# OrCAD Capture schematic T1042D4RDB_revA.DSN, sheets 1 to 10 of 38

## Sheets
1 01 Page Listing: title: T104XRDB; rev: A
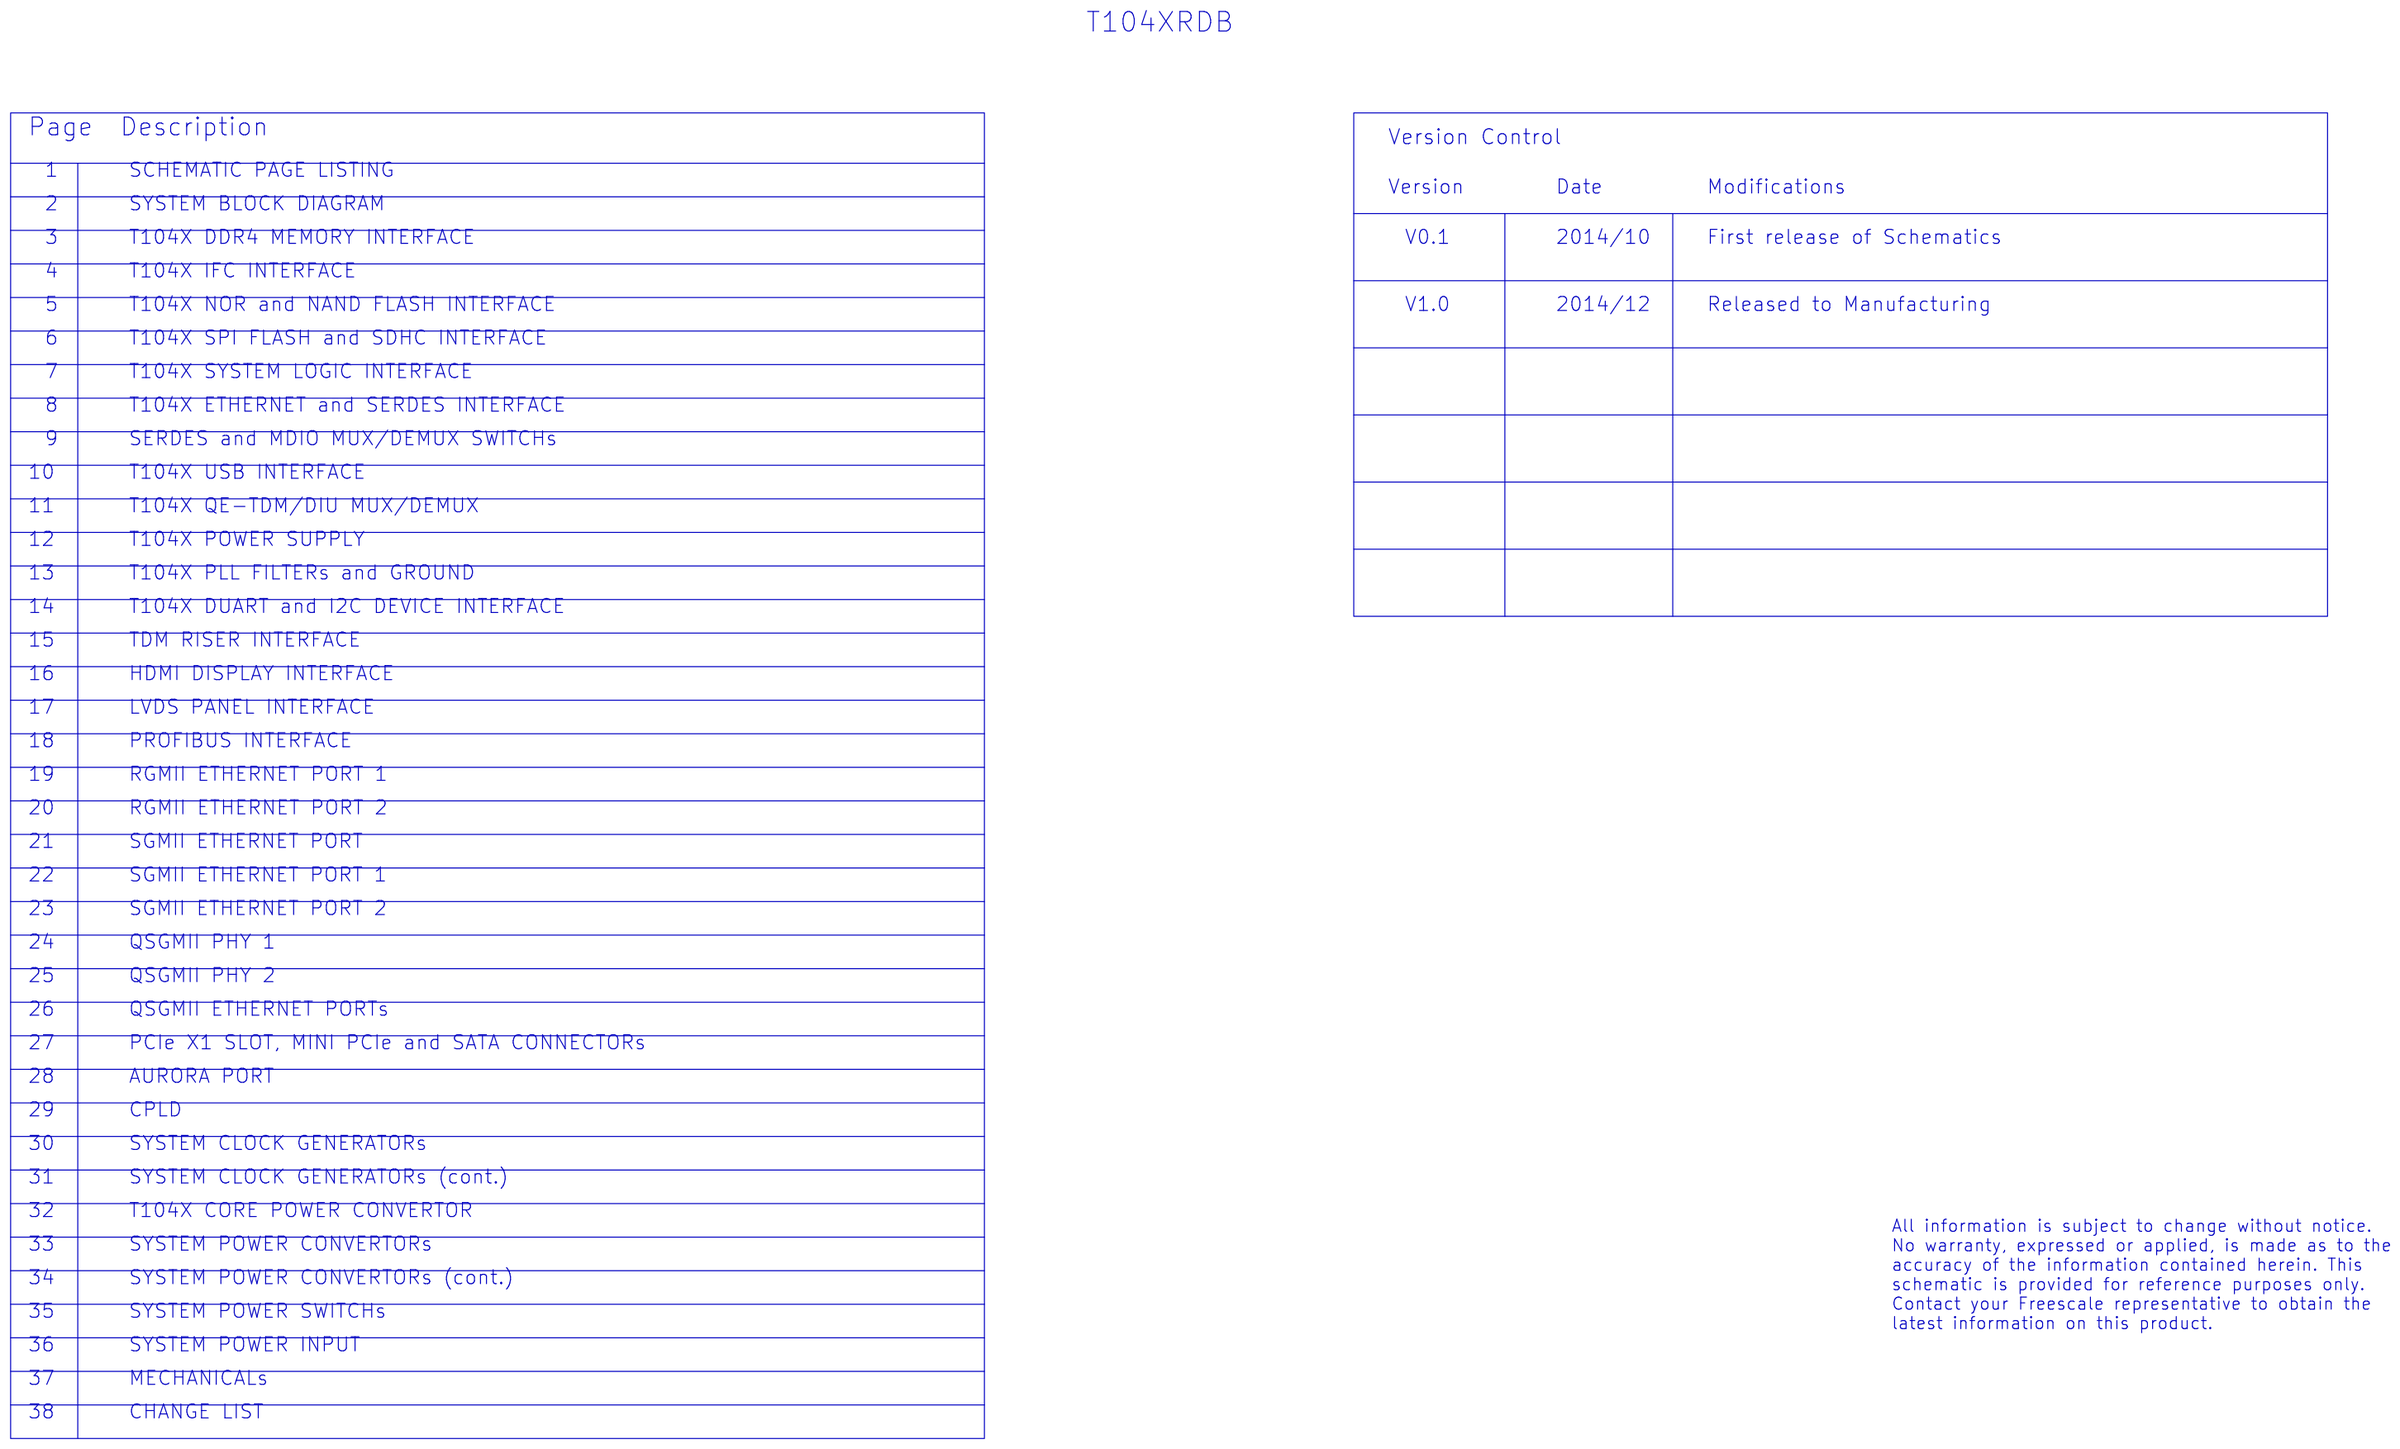
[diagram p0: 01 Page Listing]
2 02 Block Diagram
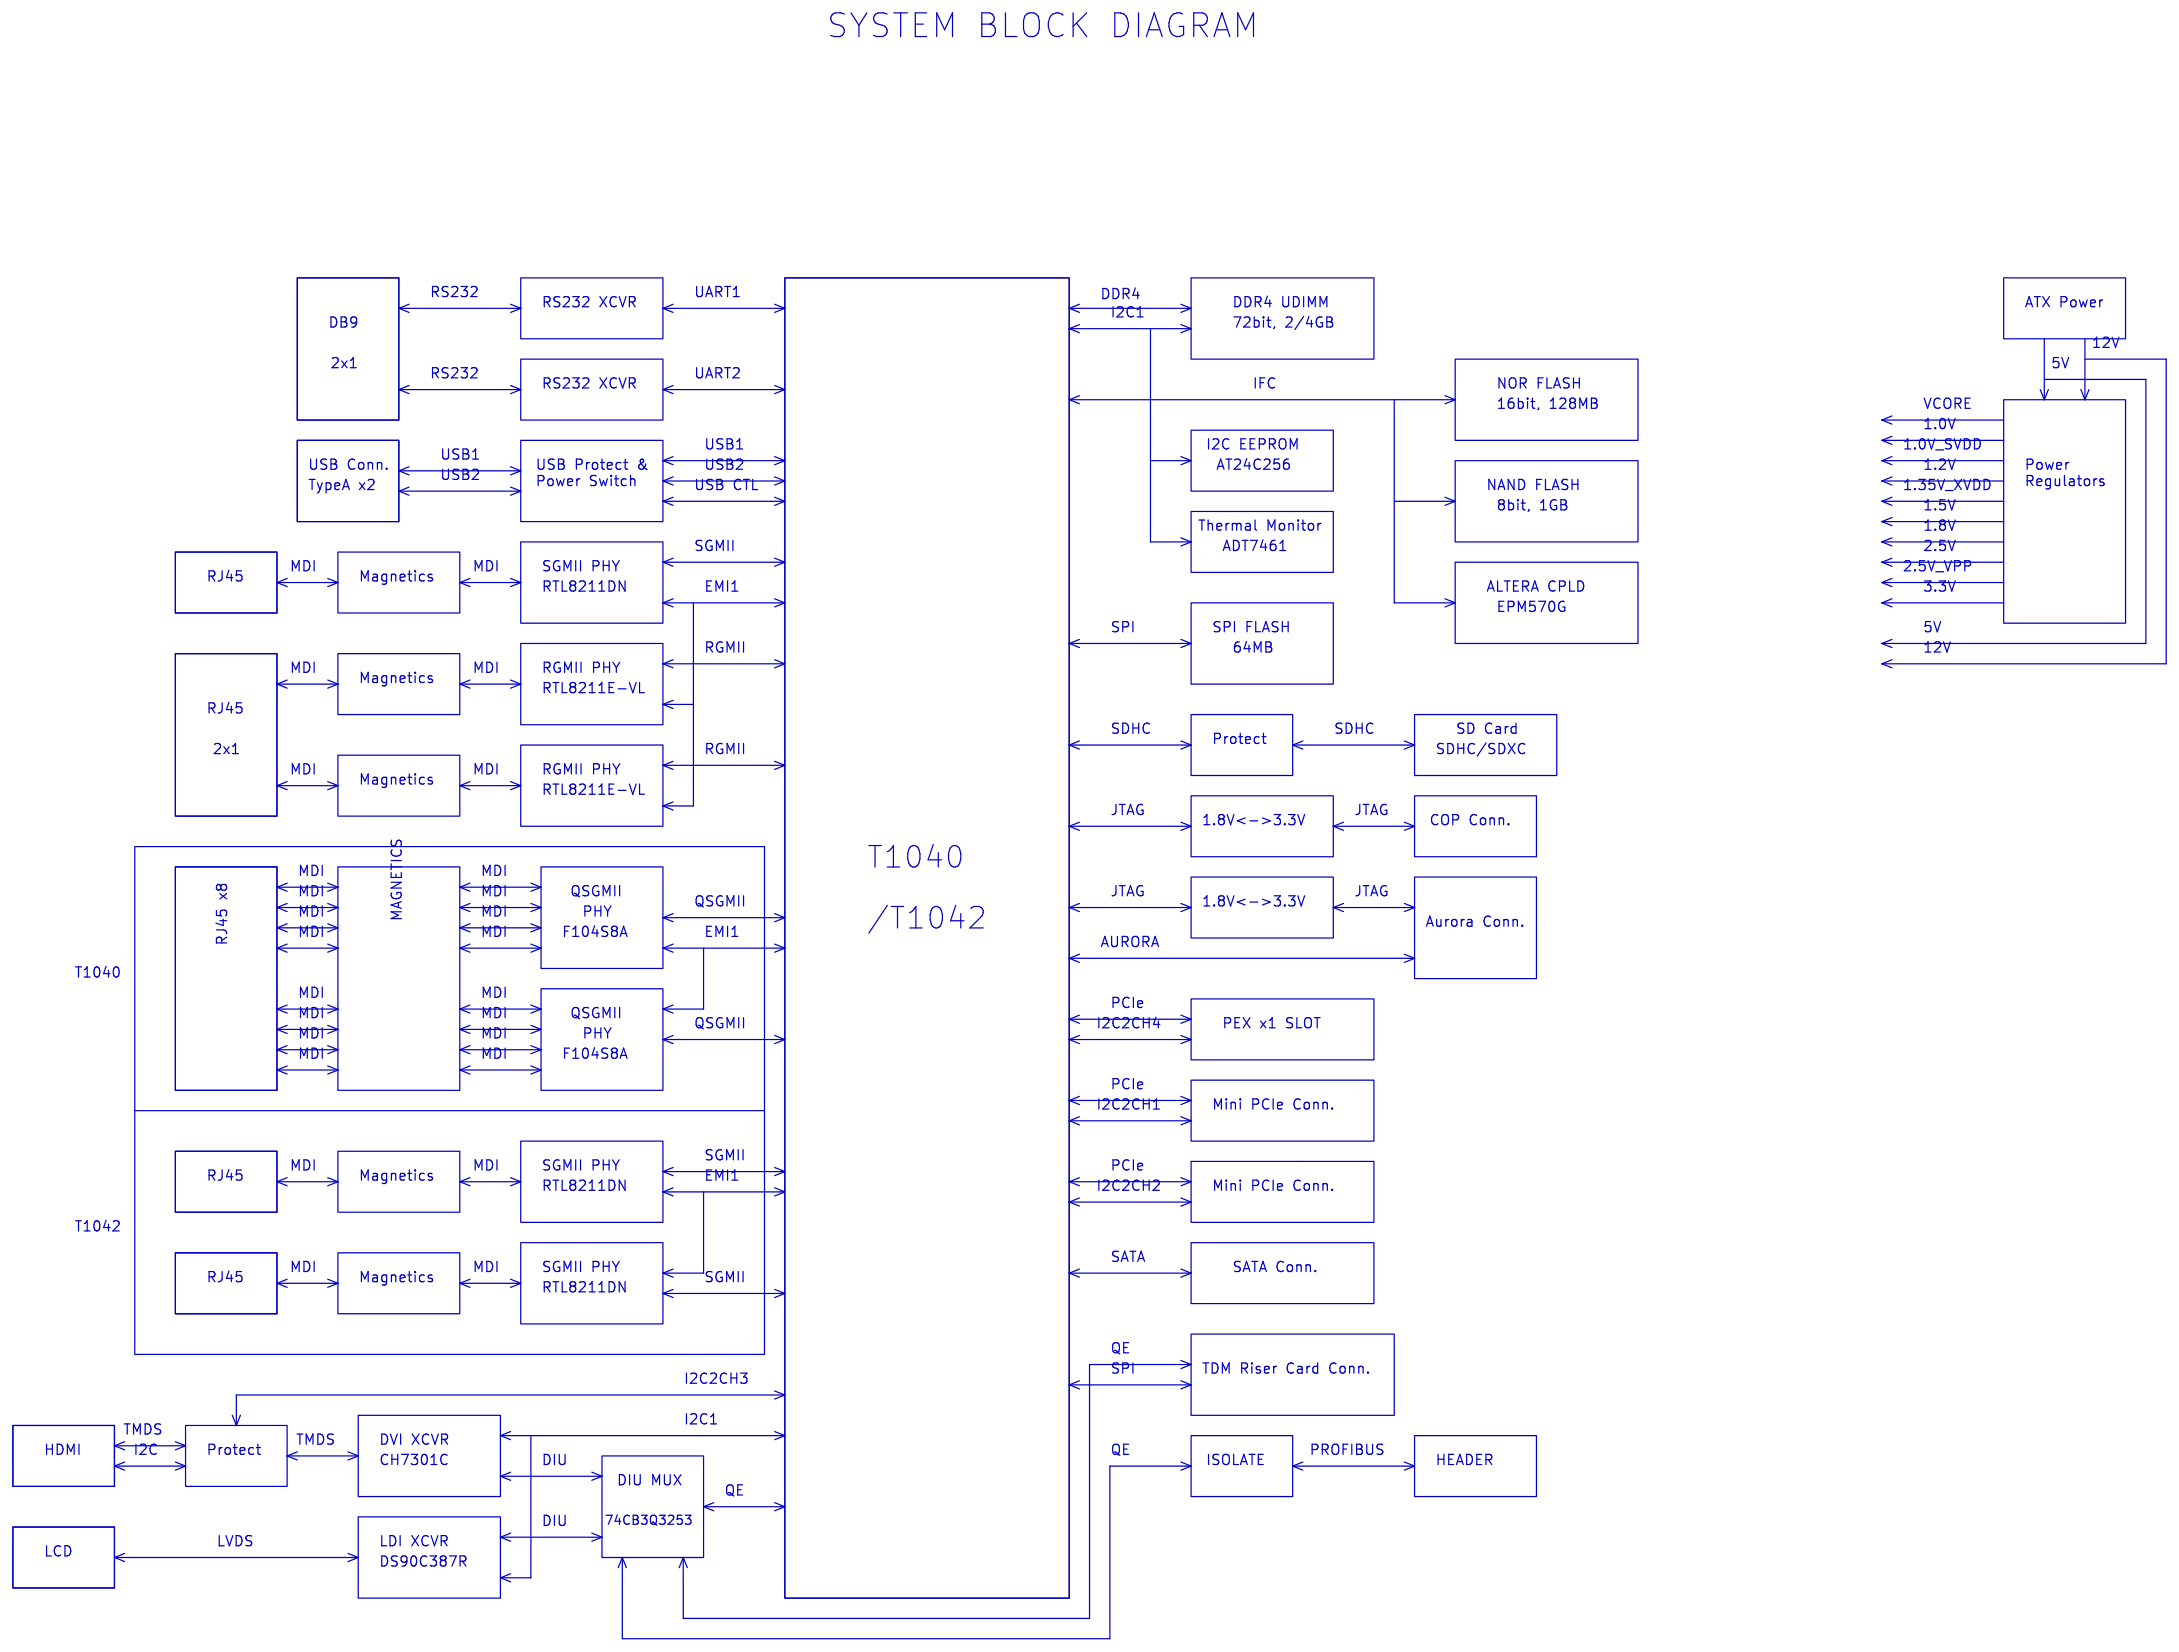
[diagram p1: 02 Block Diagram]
3 03 DDR4: size B
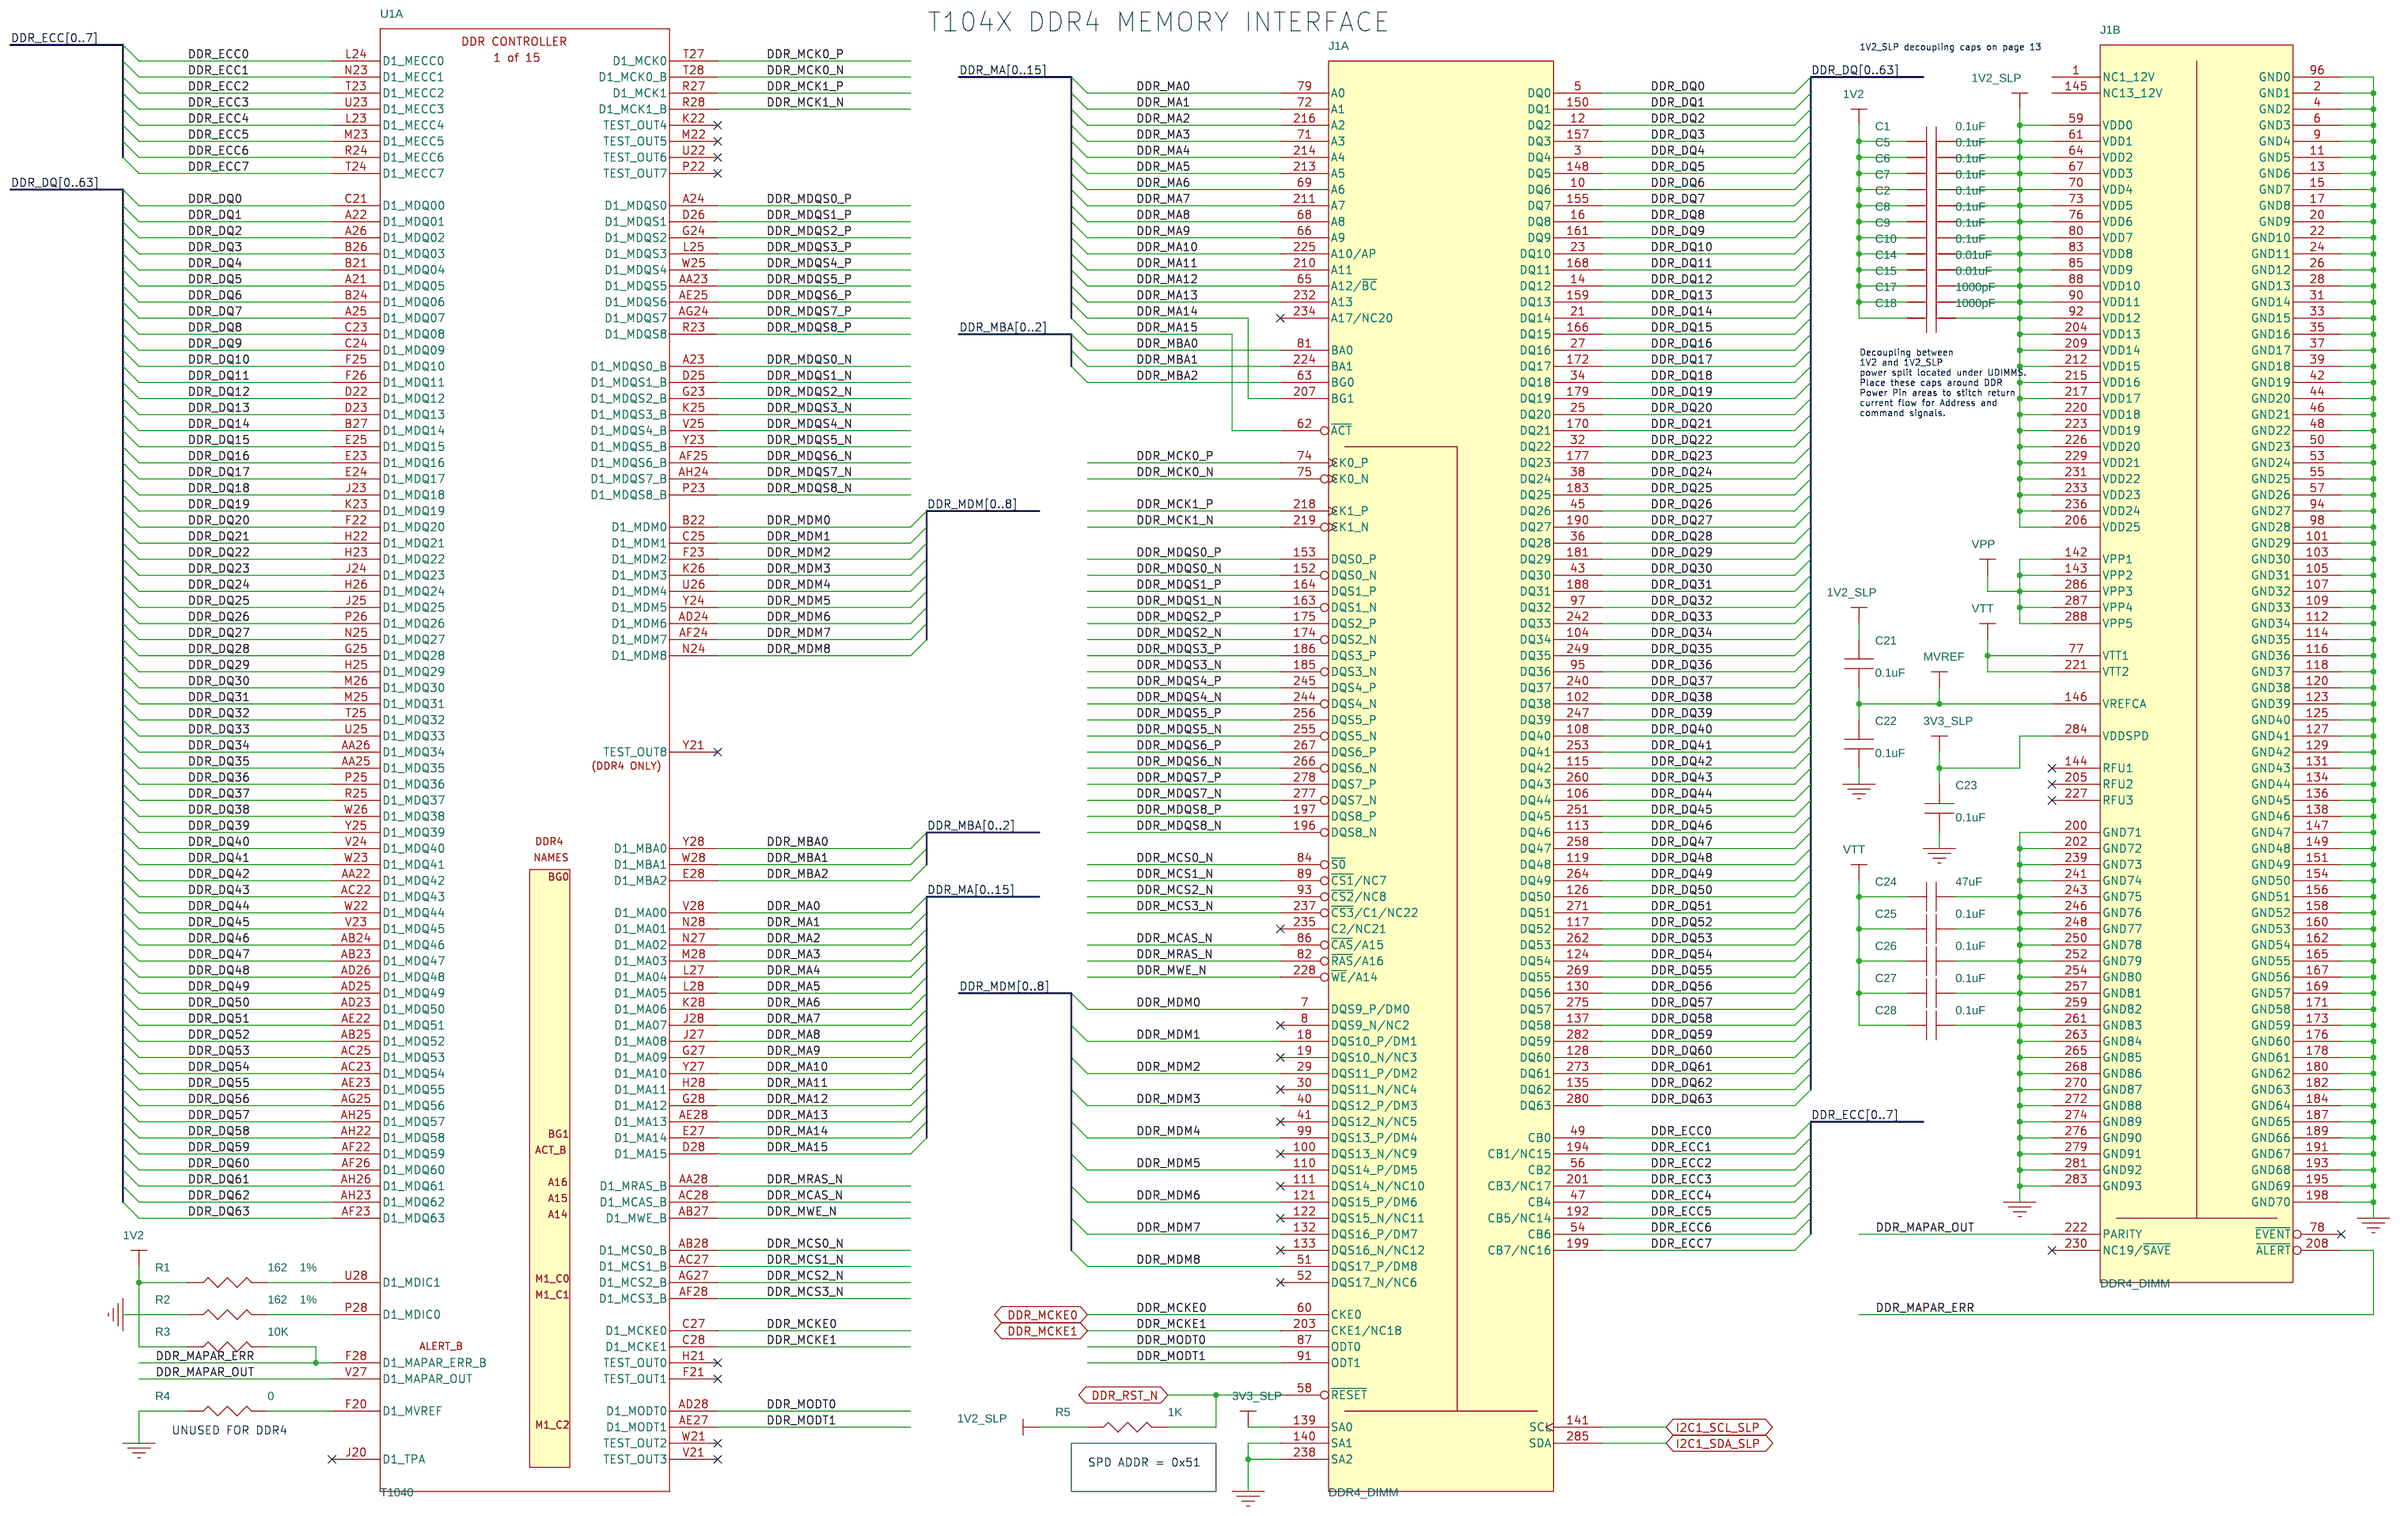
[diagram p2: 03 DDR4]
4 04 IFC: size B
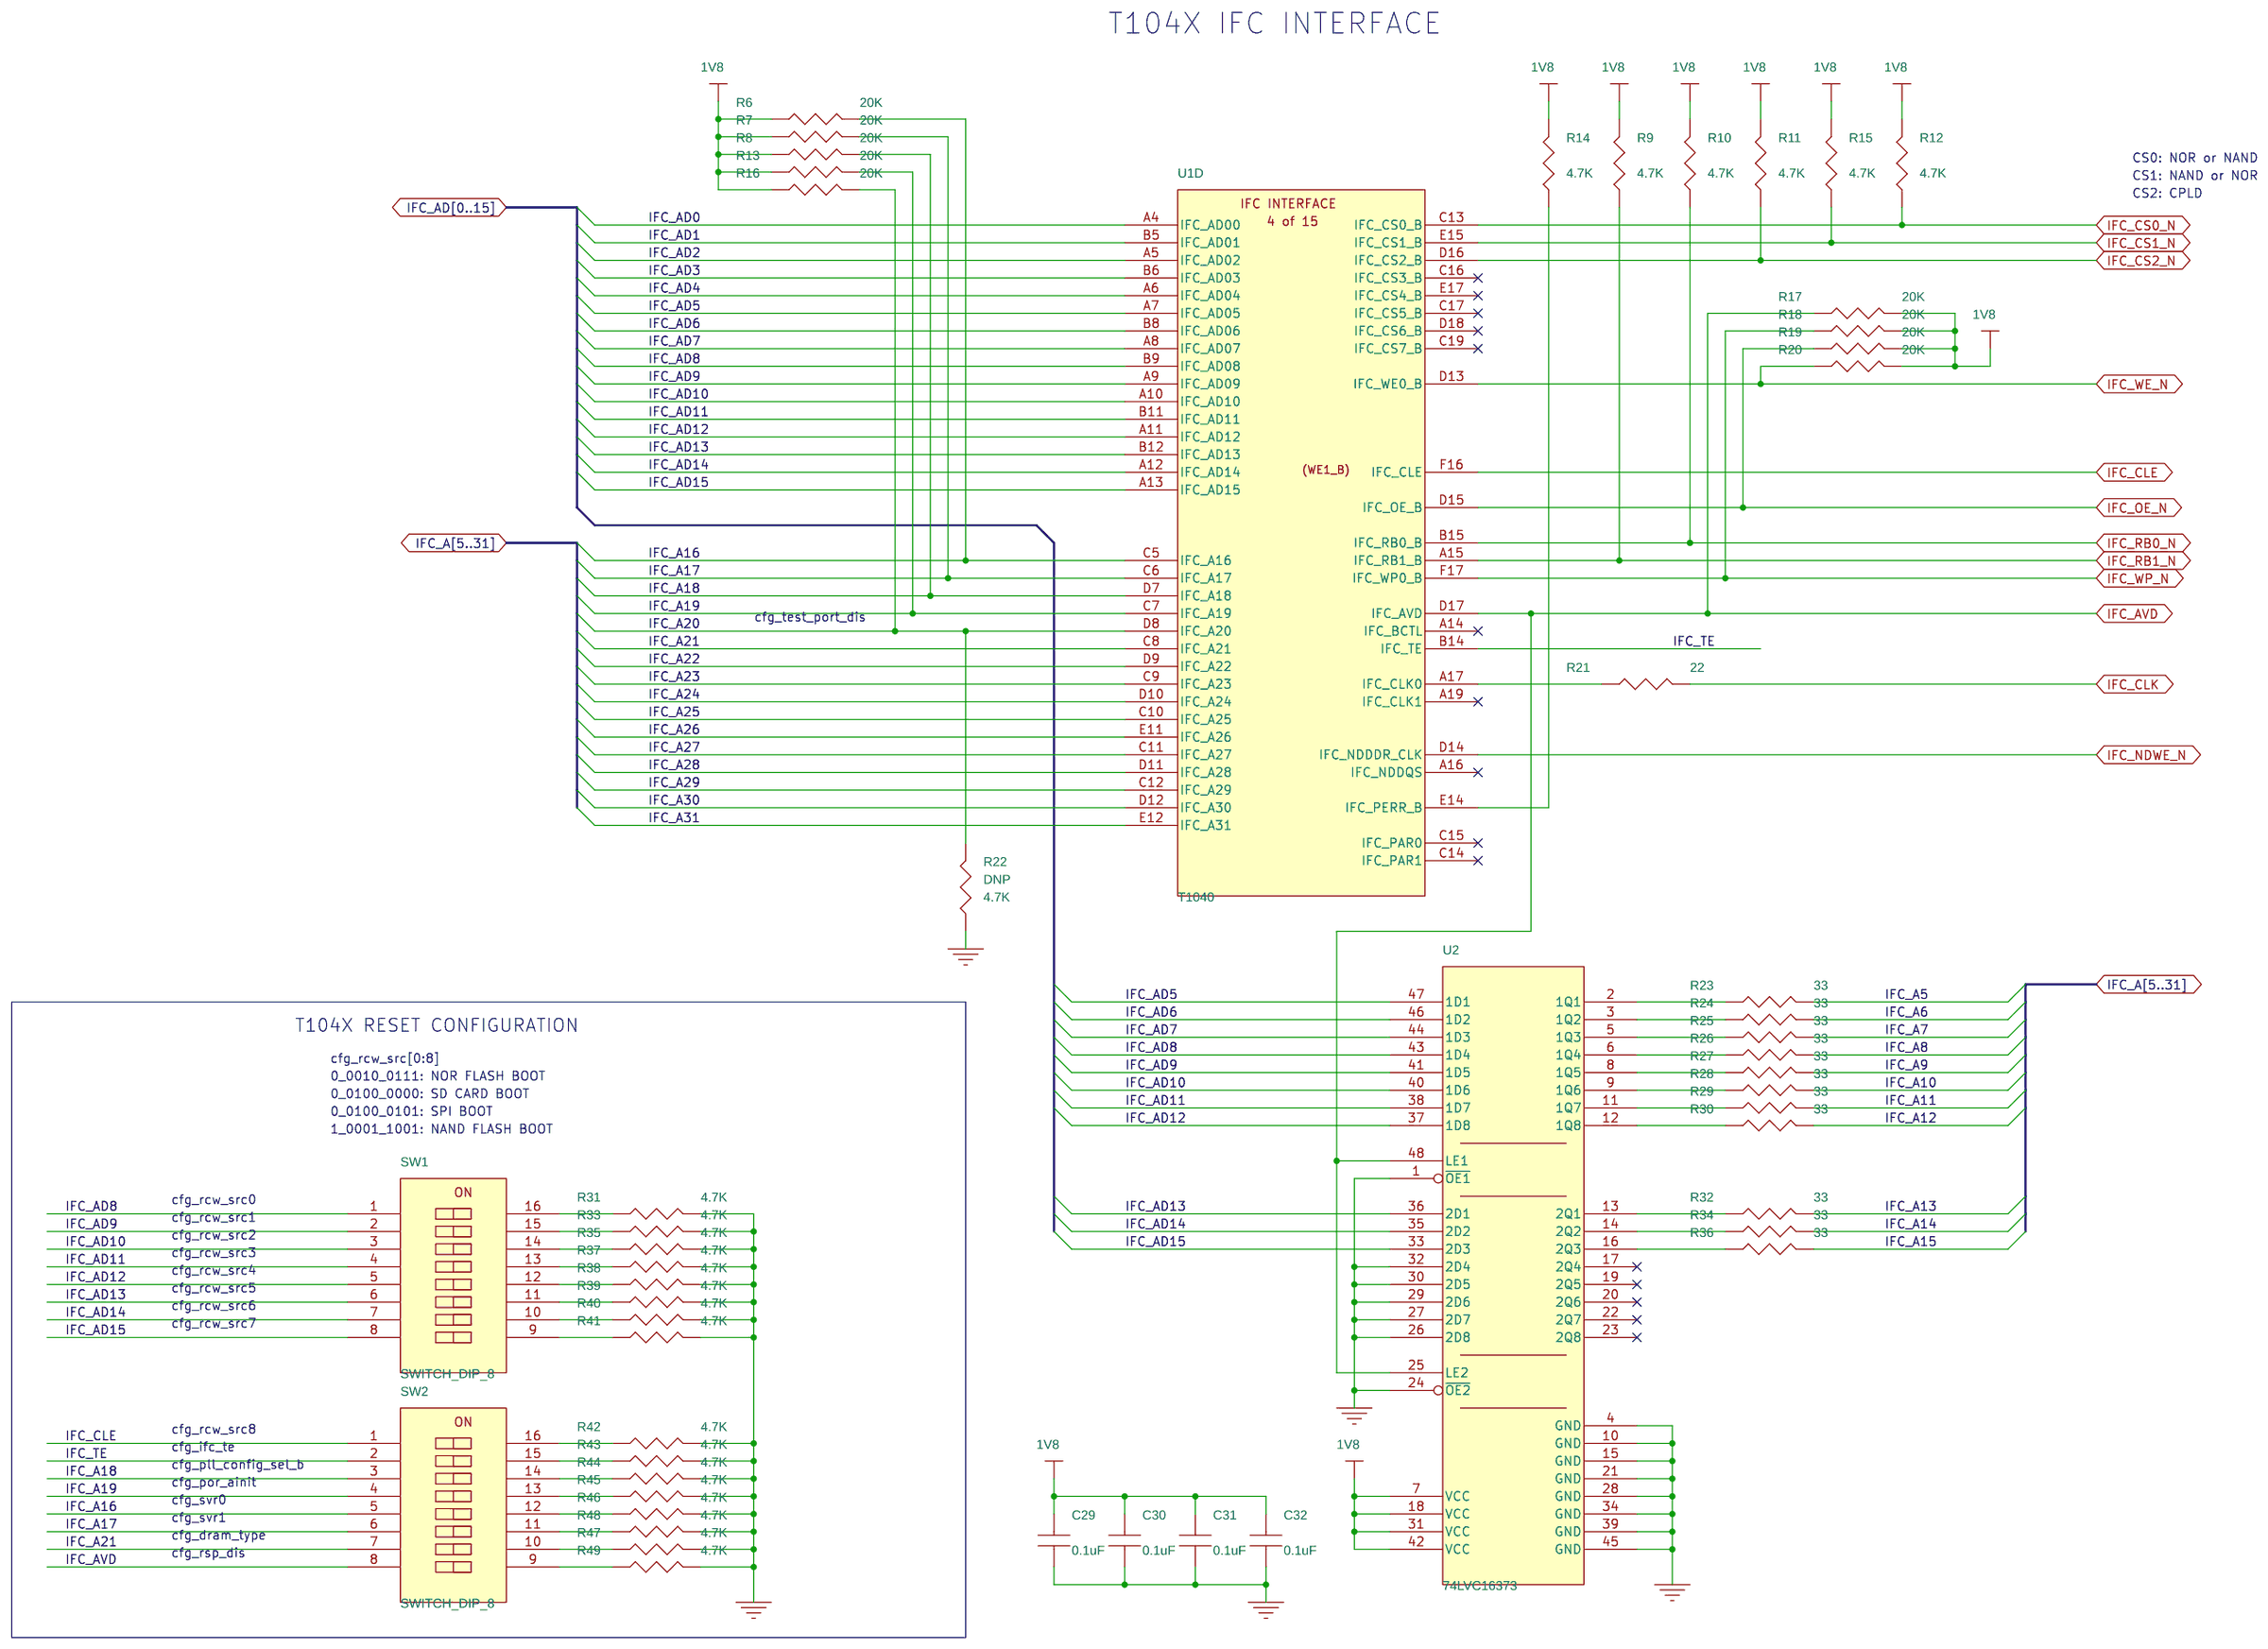
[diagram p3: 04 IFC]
5 05 Flash: size B
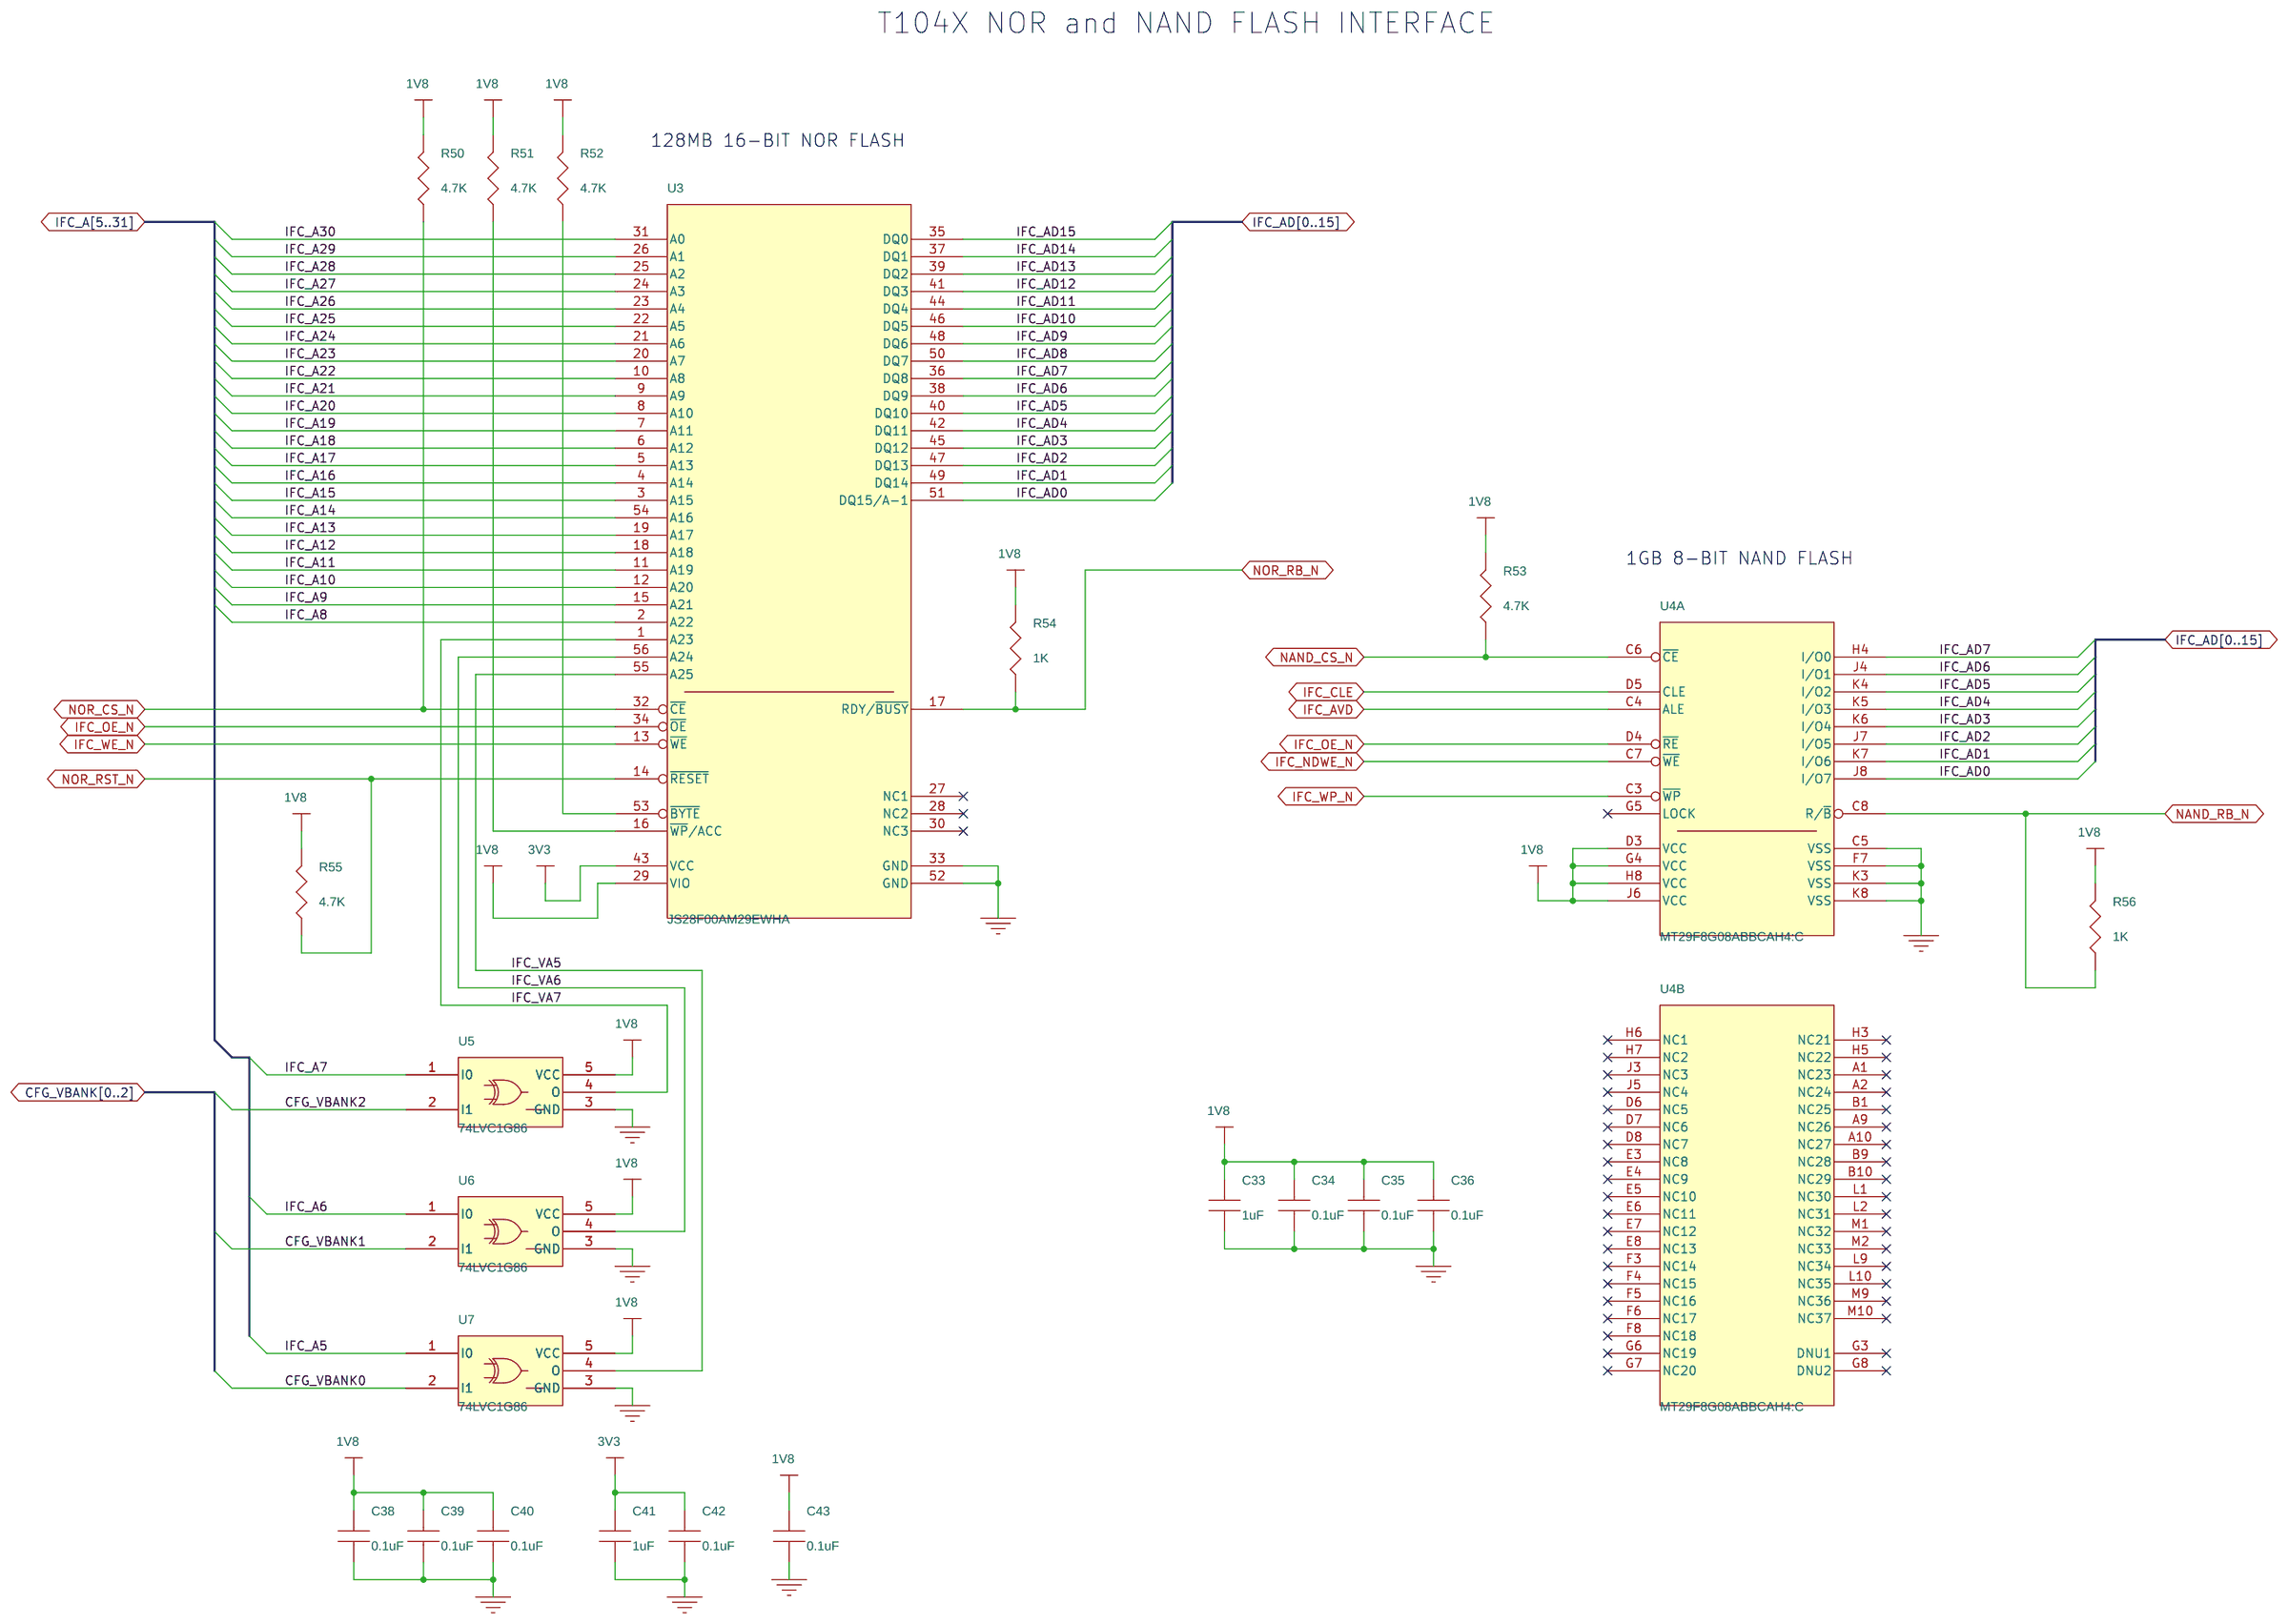
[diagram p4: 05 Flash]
6 06 SPI&SDHC: size B
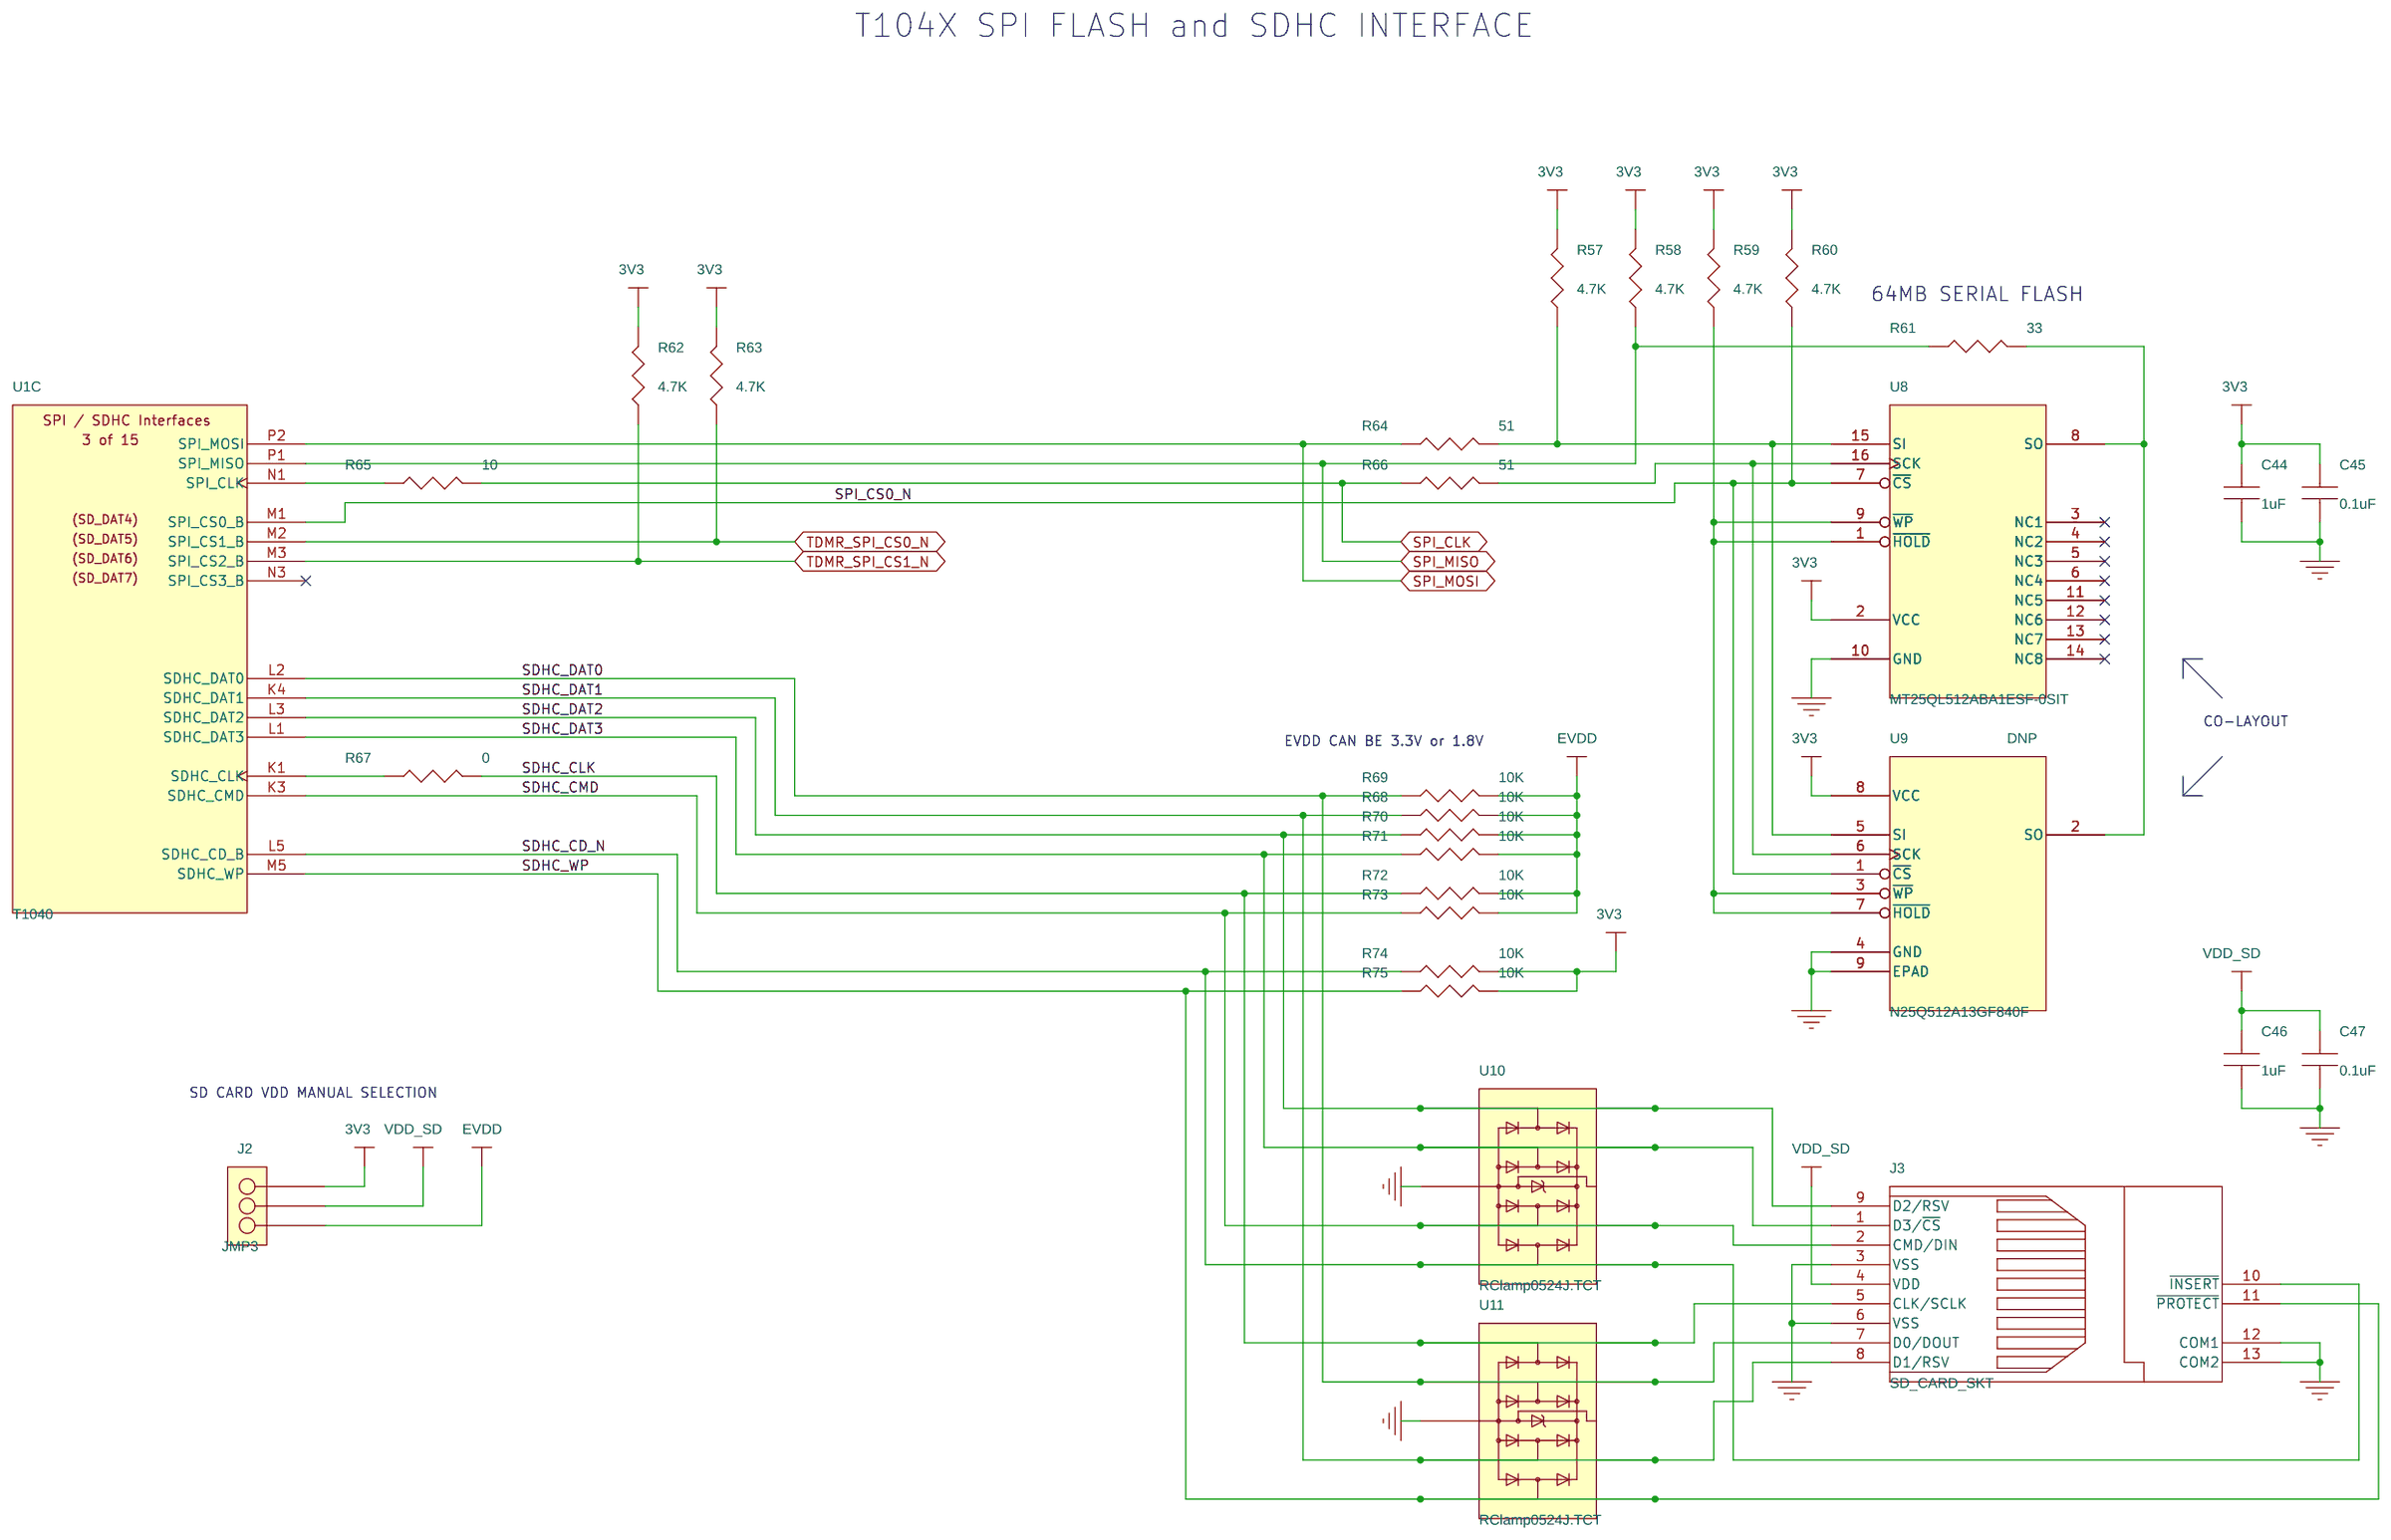
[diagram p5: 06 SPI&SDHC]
7 07 SYS: size B
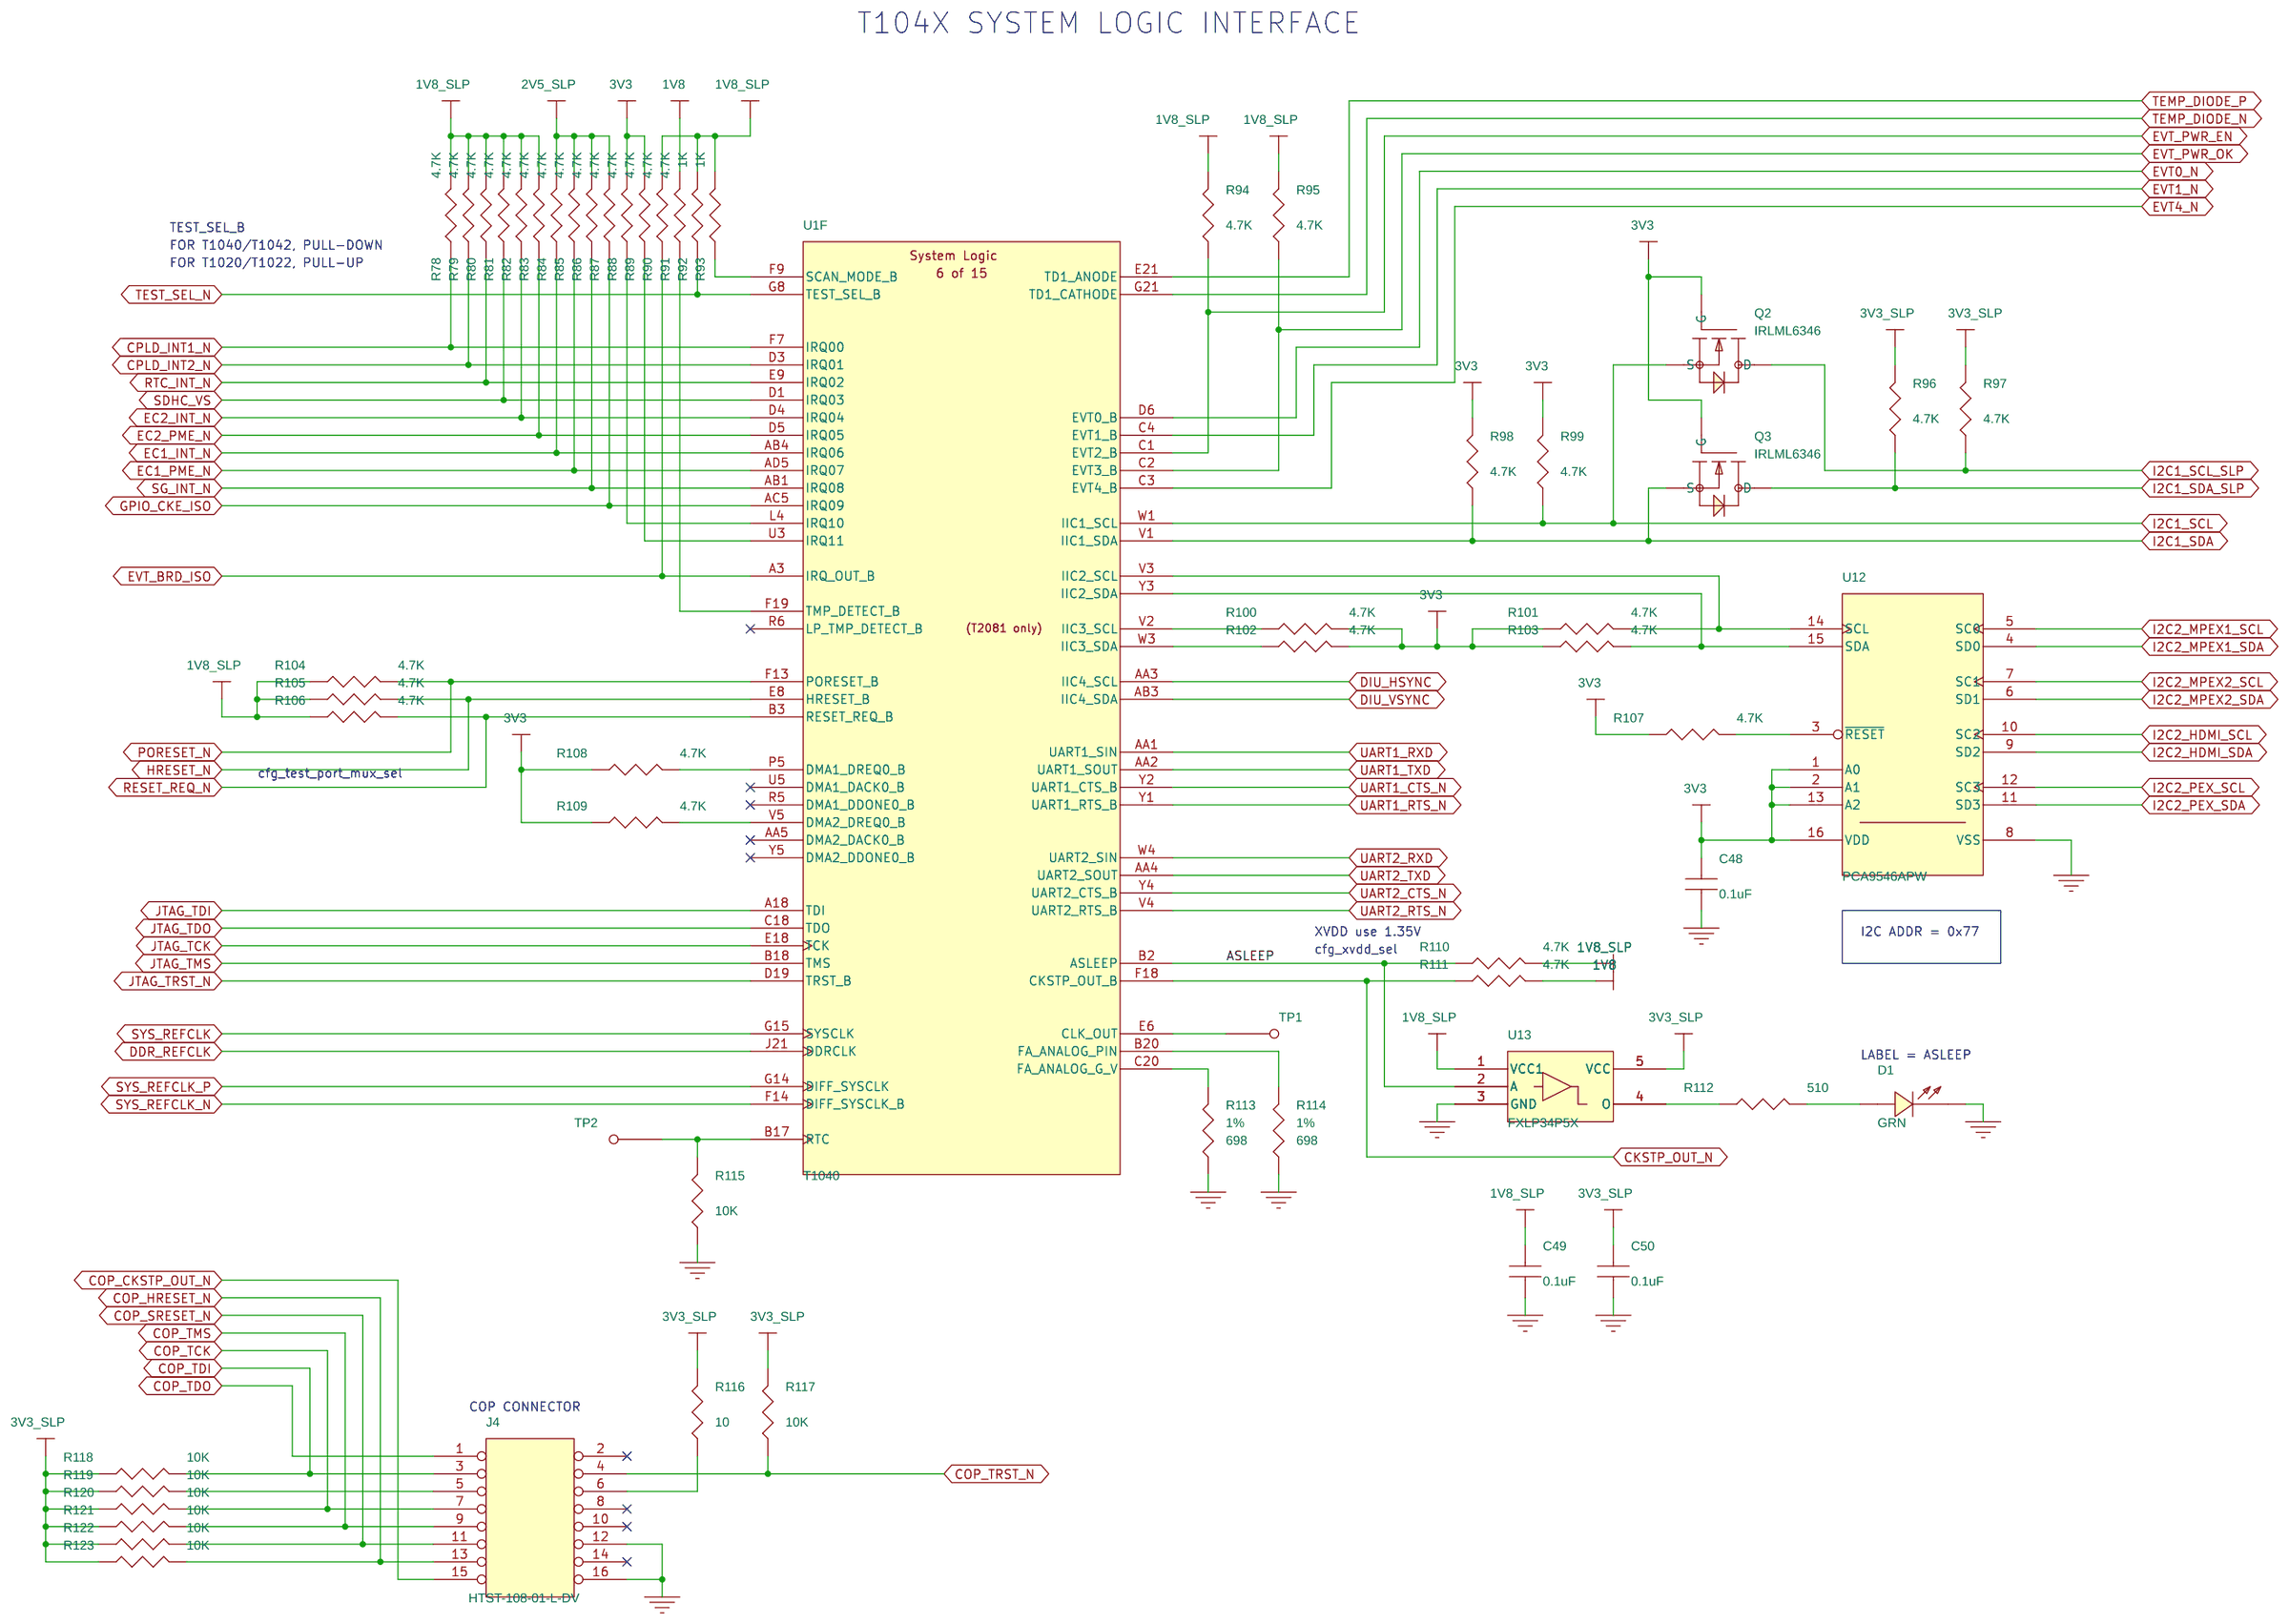
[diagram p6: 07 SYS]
8 08 EC&SD: size B
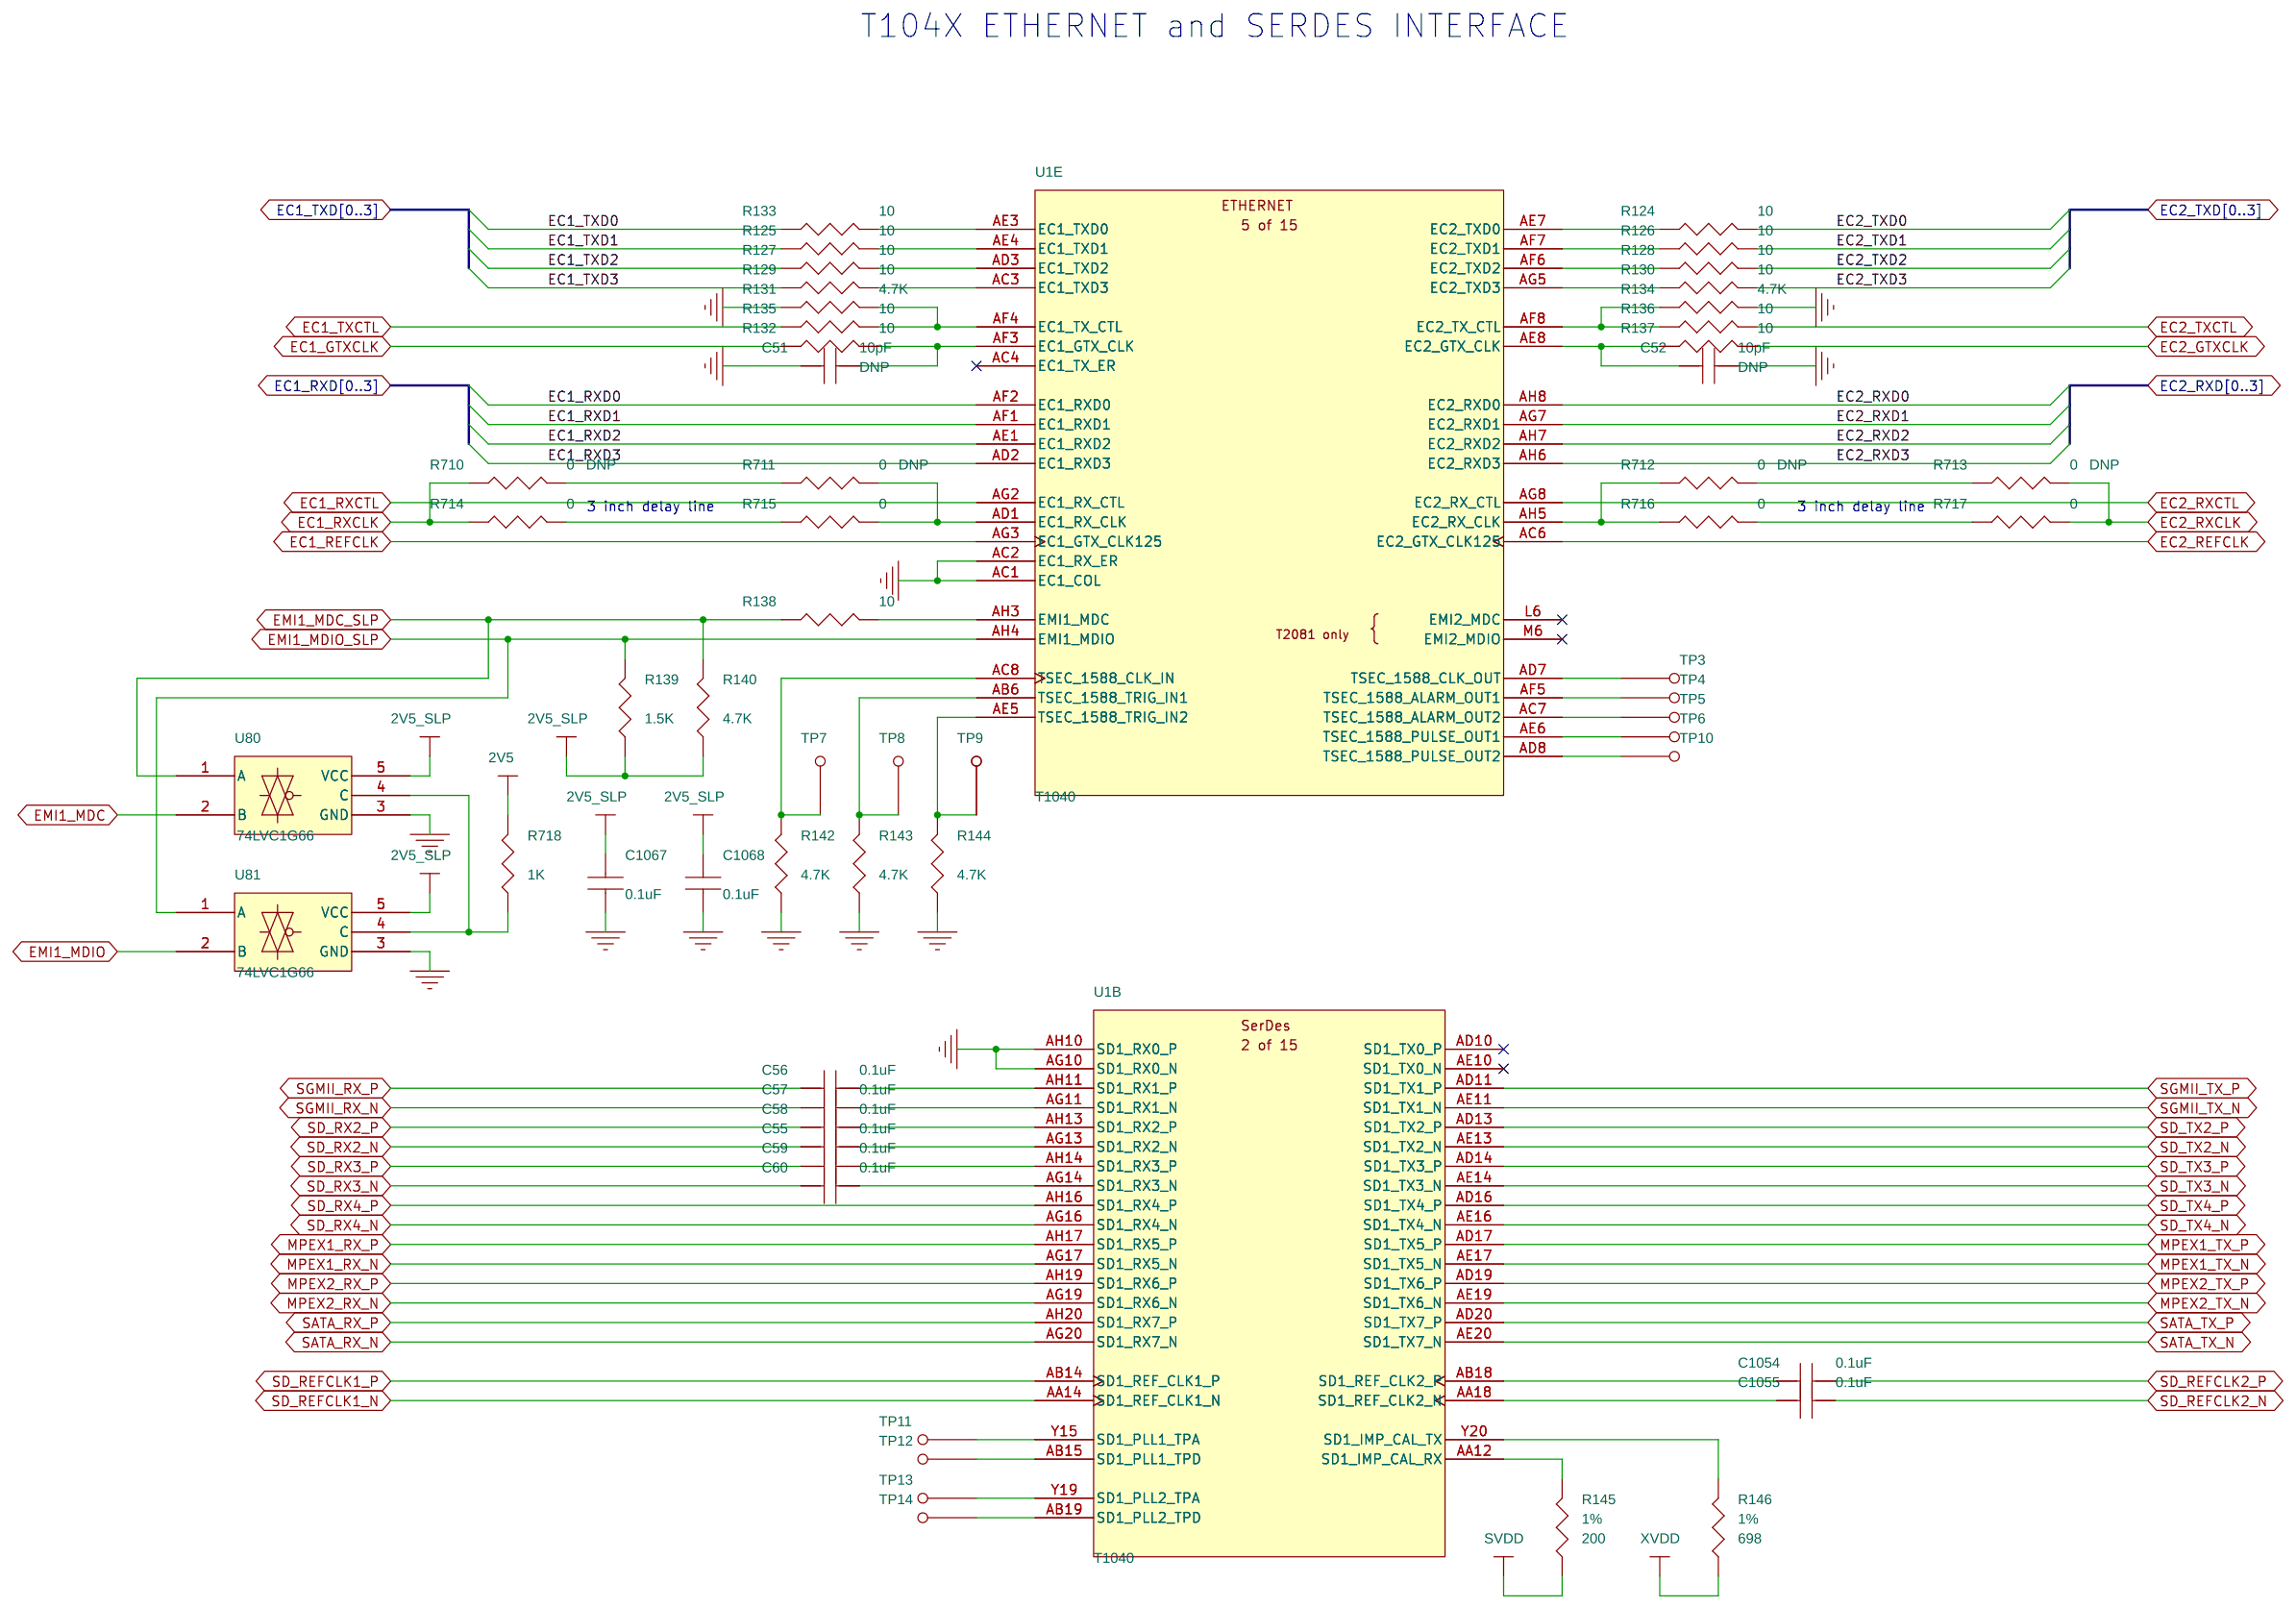
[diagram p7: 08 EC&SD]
9 09 SerDes Mux: size B
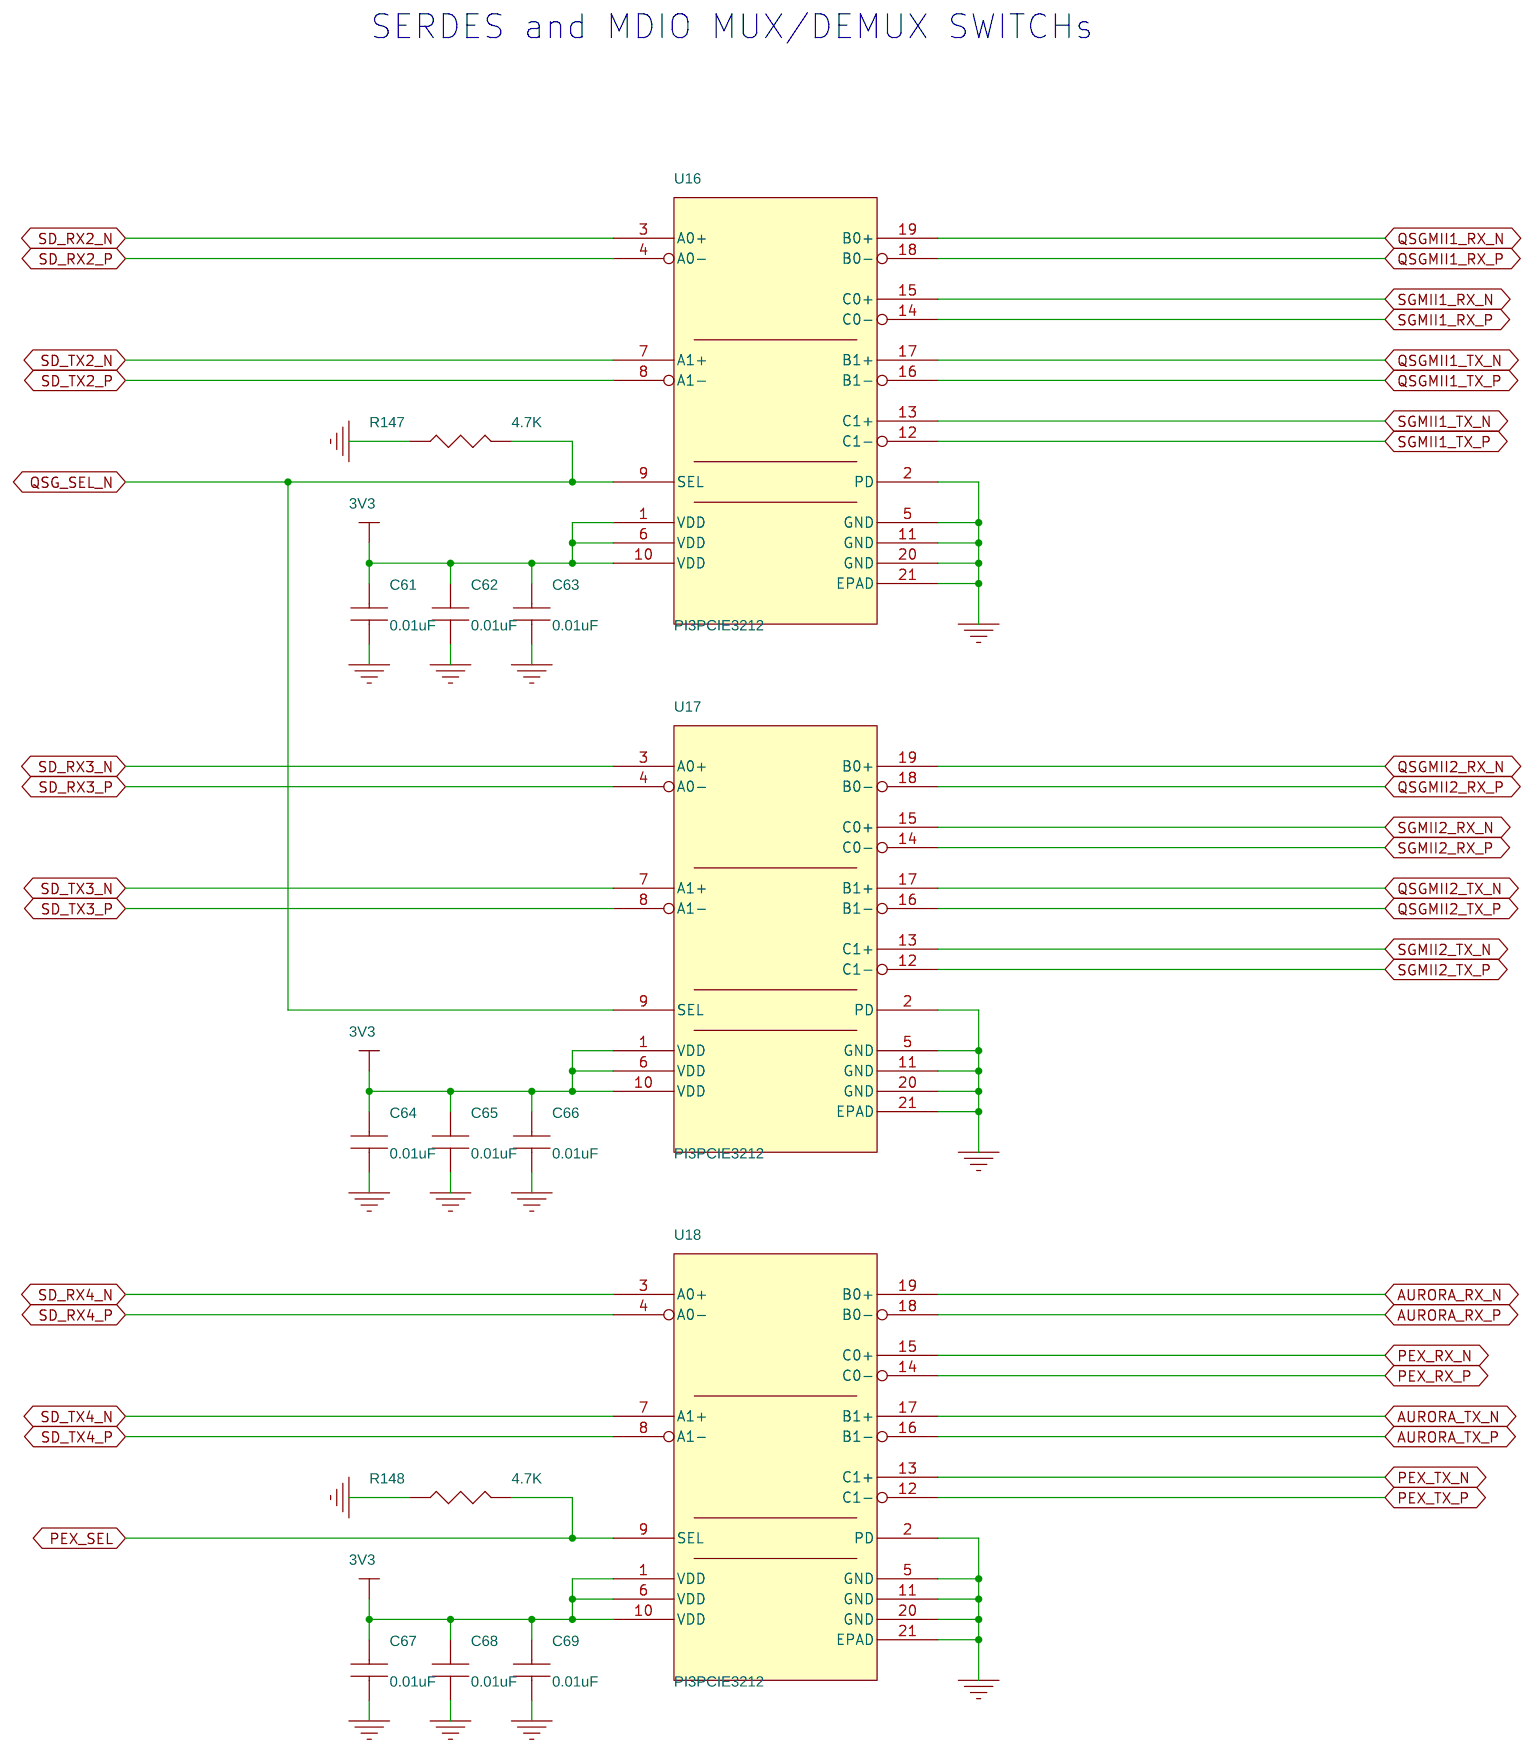
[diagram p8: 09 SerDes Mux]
10 10 USB: size B
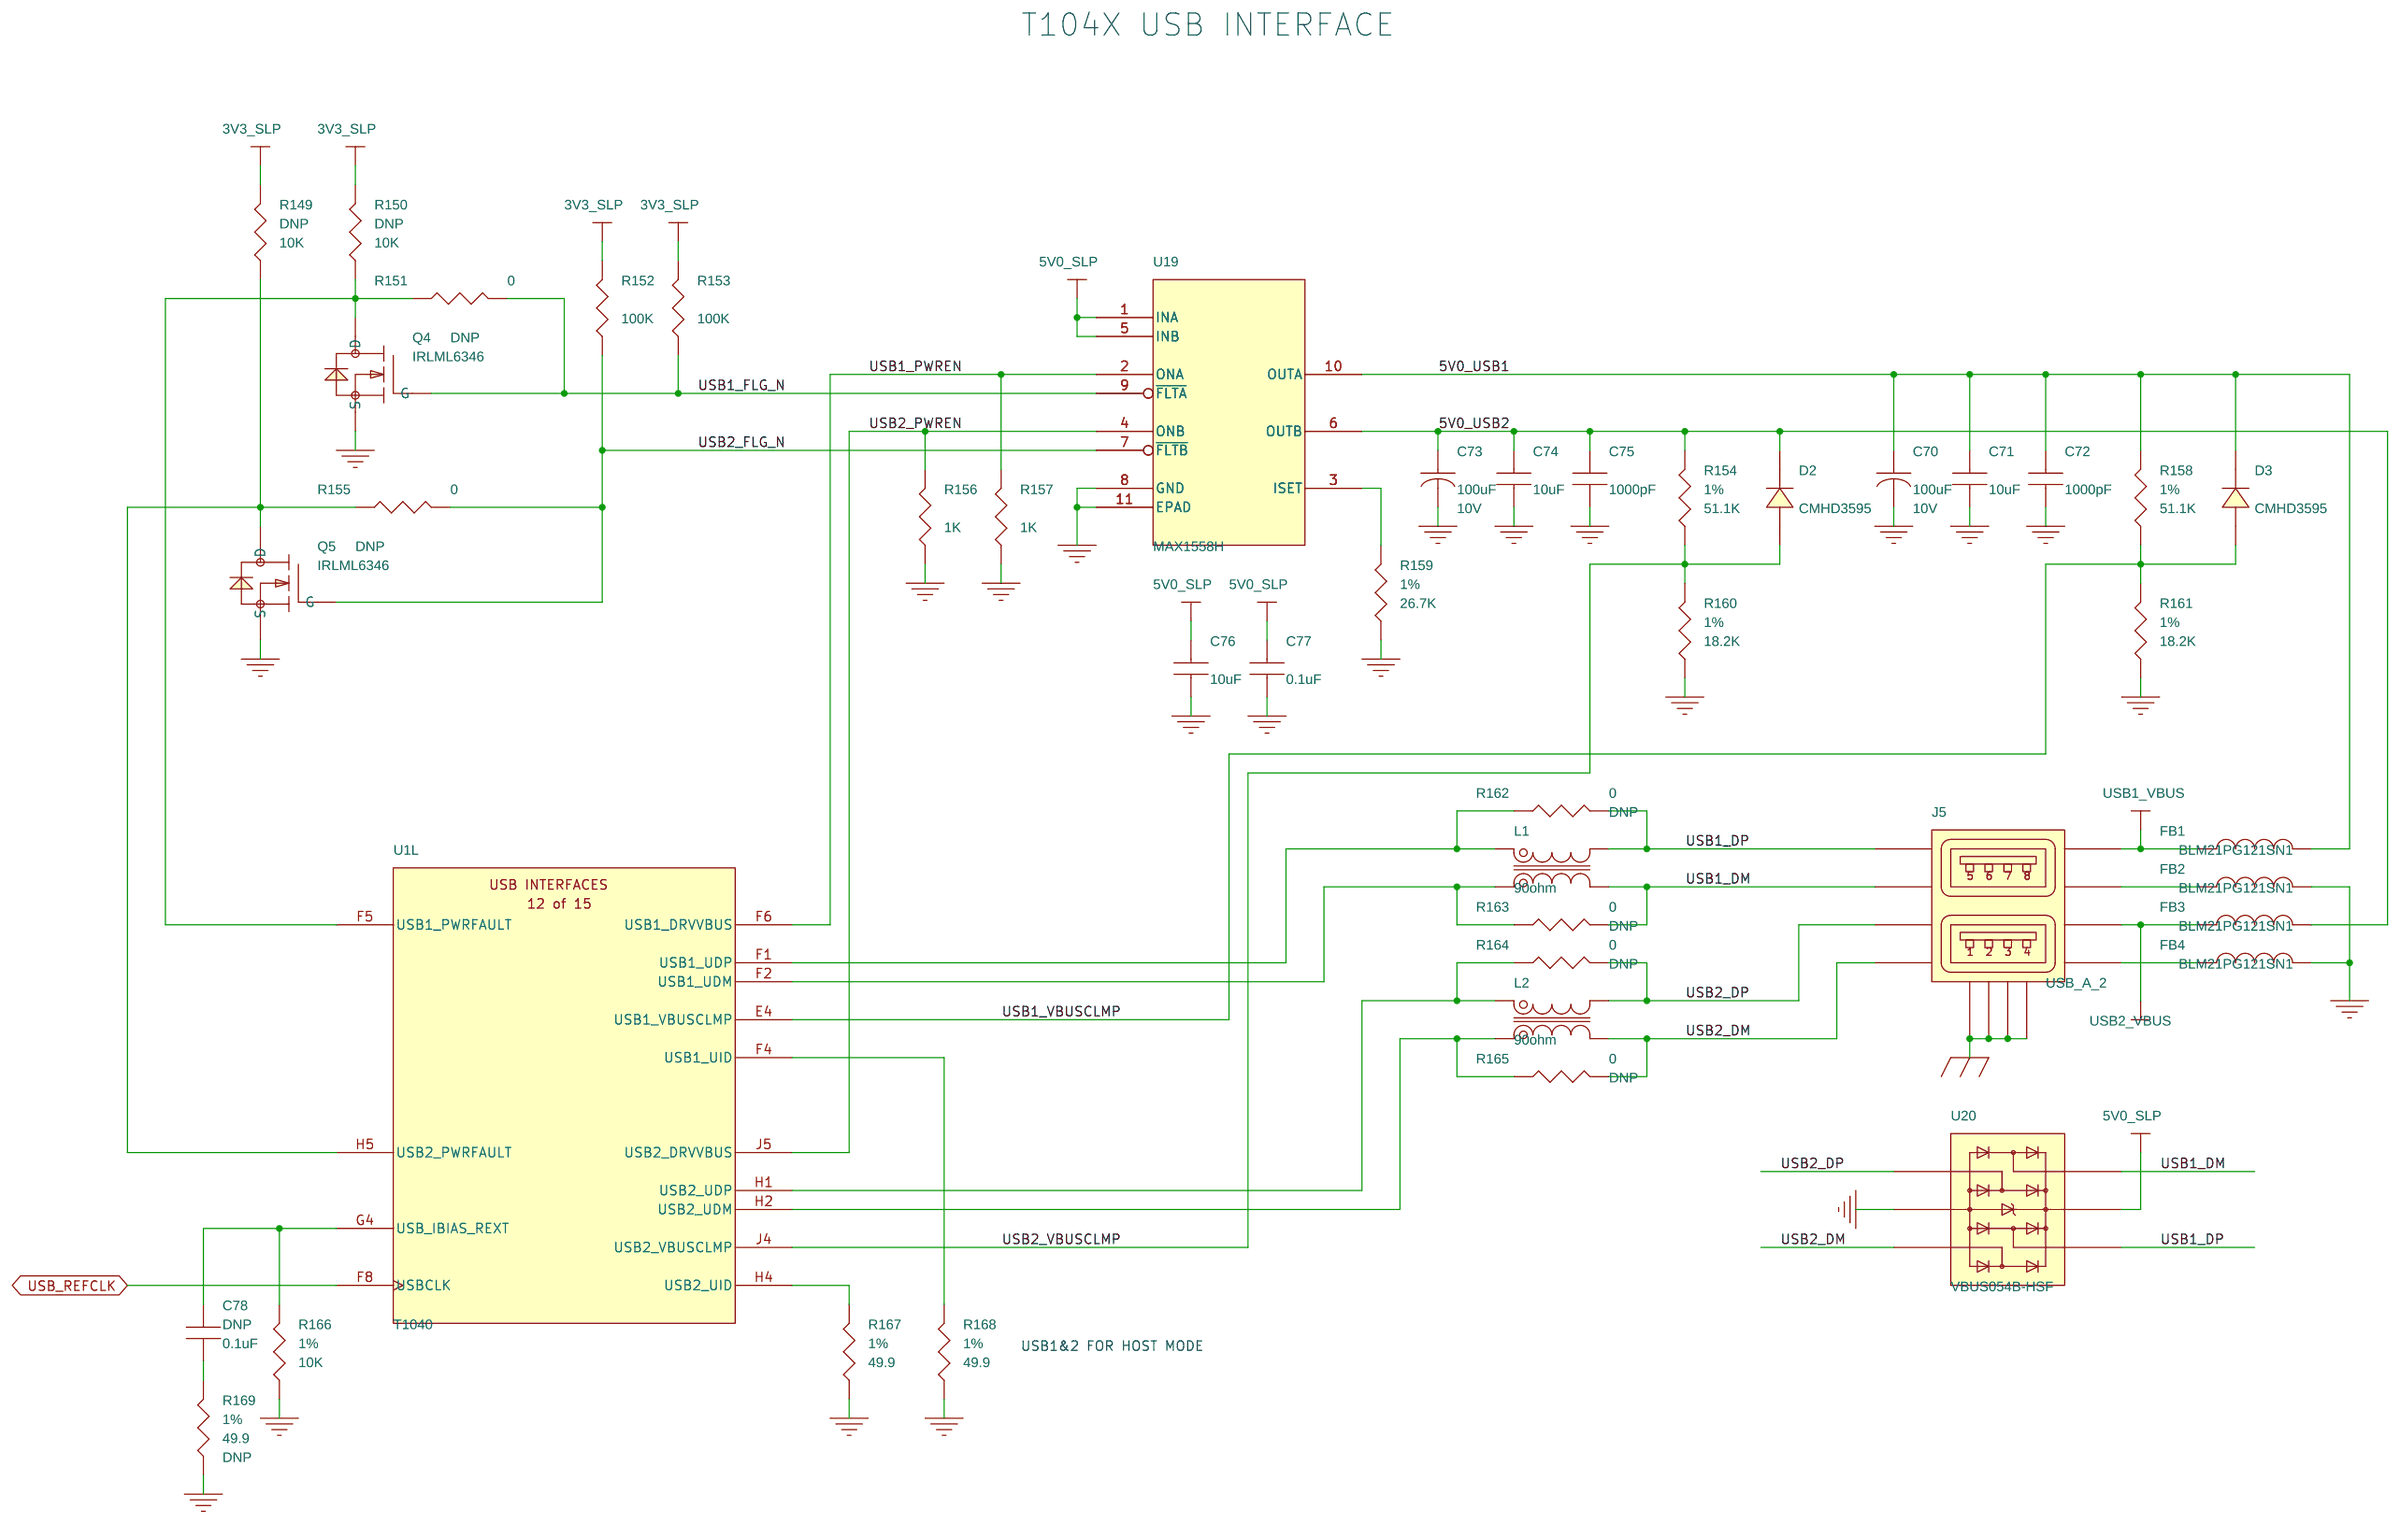
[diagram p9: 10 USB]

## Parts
sheet 03 DDR4
C1  0.1uF  [0402]
C2  0.1uF  [0402]
C5  0.1uF  [0402]
C6  0.1uF  [0402]
C7  0.1uF  [0402]
C8  0.1uF  [0402]
C9  0.1uF  [0402]
C10  0.1uF  [0402]
C14  0.01uF  [0402]
C15  0.01uF  [0402]
C17  1000pF  [0402]
C18  1000pF  [0402]
C21  0.1uF  [0402]
C22  0.1uF  [0402]
C23  0.1uF  [0402]
C24  47uF  [0805]
C25  0.1uF  [0402]
C26  0.1uF  [0402]
C27  0.1uF  [0402]
C28  0.1uF  [0402]
J1  DDR4_DIMM  [con_ddr4_dimm]  (sections A,B)
R1  162  [0402]
R2  162  [0402]
R3  10K  [0402]
R4  0  [0402]
R5  1K  [0402]
sheet 04 IFC
C29  0.1uF  [0402]
C30  0.1uF  [0402]
C31  0.1uF  [0402]
C32  0.1uF  [0402]
R6  20K  [0402]
R7  20K  [0402]
R8  20K  [0402]
R9  4.7K  [0402]
R10  4.7K  [0402]
R11  4.7K  [0402]
R12  4.7K  [0402]
R13  20K  [0402]
R14  4.7K  [0402]
R15  4.7K  [0402]
R16  20K  [0402]
R17  20K  [0402]
R18  20K  [0402]
R19  20K  [0402]
R20  20K  [0402]
R21  22  [0402]
R22  4.7K  [0402]
R23  33  [0402]
R24  33  [0402]
R25  33  [0402]
R26  33  [0402]
R27  33  [0402]
R28  33  [0402]
R29  33  [0402]
R30  33  [0402]
R31  4.7K  [0402]
R32  33  [0402]
R33  4.7K  [0402]
R34  33  [0402]
R35  4.7K  [0402]
R36  33  [0402]
R37  4.7K  [0402]
R38  4.7K  [0402]
R39  4.7K  [0402]
R40  4.7K  [0402]
R41  4.7K  [0402]
R42  4.7K  [0402]
R43  4.7K  [0402]
R44  4.7K  [0402]
R45  4.7K  [0402]
R46  4.7K  [0402]
R47  4.7K  [0402]
R48  4.7K  [0402]
R49  4.7K  [0402]
SW1  SWITCH_DIP_8  [con_switch_x8]
SW2  SWITCH_DIP_8  [con_switch_x8]
U2  74LVC16373  [tssop_48w]
sheet 05 Flash
C33  1uF  [0402]
C34  0.1uF  [0402]
C35  0.1uF  [0402]
C36  0.1uF  [0402]
C38  0.1uF  [0402]
C39  0.1uF  [0402]
C40  0.1uF  [0402]
C41  1uF  [0402]
C42  0.1uF  [0402]
C43  0.1uF  [0402]
R50  4.7K  [0402]
R51  4.7K  [0402]
R52  4.7K  [0402]
R53  4.7K  [0402]
R54  1K  [0402]
R55  4.7K  [0402]
R56  1K  [0402]
U3  JS28F00AM29EWHA  [tsop1_56]
U4  MT29F8G08ABBCAH4:C  [bga_p080_nand_63]  (sections A,B)
U5  74LVC1G86  [sc70_5]
U6  74LVC1G86  [sc70_5]
U7  74LVC1G86  [sc70_5]
sheet 06 SPI&SDHC
C44  1uF  [0402]
C45  0.1uF  [0402]
C46  1uF  [0402]
C47  0.1uF  [0402]
J2  JMP3  [jmp_p254_t_1x3]
J3  SD_CARD_SKT  [con_sd]
R57  4.7K  [0402]
R58  4.7K  [0402]
R59  4.7K  [0402]
R60  4.7K  [0402]
R61  33  [0402]
R62  4.7K  [0402]
R63  4.7K  [0402]
R64  51  [0402]
R65  10  [0402]
R66  51  [0402]
R67  0  [0402]
R68  10K  [0402]
R69  10K  [0402]
R70  10K  [0402]
R71  10K  [0402]
R72  10K  [0402]
R73  10K  [0402]
R74  10K  [0402]
R75  10K  [0402]
U8  MT25QL512ABA1ESF-0SIT  [so_16l]
U9  N25Q512A13GF840F  [wson_8]
U10  RClamp0524J.TCT  [tvs_slp2710p8]
U11  RClamp0524J.TCT  [tvs_slp2710p8]
sheet 07 SYS
C48  0.1uF  [0402]
C49  0.1uF  [0402]
C50  0.1uF  [0402]
D1  GRN  [led_0603]
J4  HTST-108-01-L-DV  [hdr_p254_htst_2x8]
Q2  IRLML6346  [sot23]
Q3  IRLML6346  [sot23]
R78  4.7K  [0402]
R79  4.7K  [0402]
R80  4.7K  [0402]
R81  4.7K  [0402]
R82  4.7K  [0402]
R83  4.7K  [0402]
R84  4.7K  [0402]
R85  4.7K  [0402]
R86  4.7K  [0402]
R87  4.7K  [0402]
R88  4.7K  [0402]
R89  4.7K  [0402]
R90  4.7K  [0402]
R91  4.7K  [0402]
R92  1K  [0402]
R93  1K  [0402]
R94  4.7K  [0402]
R95  4.7K  [0402]
R96  4.7K  [0402]
R97  4.7K  [0402]
R98  4.7K  [0402]
R99  4.7K  [0402]
R100  4.7K  [0402]
R101  4.7K  [0402]
R102  4.7K  [0402]
R103  4.7K  [0402]
R104  4.7K  [0402]
R105  4.7K  [0402]
R106  4.7K  [0402]
R107  4.7K  [0402]
R108  4.7K  [0402]
R109  4.7K  [0402]
R110  4.7K  [0402]
R111  4.7K  [0402]
R112  510  [0402]
R113  698  [0402]
R114  698  [0402]
R115  10K  [0402]
R116  10  [0402]
R117  10K  [0402]
R118  10K  [0402]
R119  10K  [0402]
R120  10K  [0402]
R121  10K  [0402]
R122  10K  [0402]
R123  10K  [0402]
TP1  TP  [tp]
TP2  TP  [tp]
U1  T1040  [bga_p080_780]  (sections A,B,C,D,E,F,G,H,I,J,K,L,M,N,O)
U12  PCA9546APW  [tssop_16]
U13  FXLP34P5X  [sc70_5]
sheet 08 EC&SD
C51  10pF  [0402]
C52  10pF  [0402]
C55  0.1uF  [0402]
C56  0.1uF  [0402]
C57  0.1uF  [0402]
C58  0.1uF  [0402]
C59  0.1uF  [0402]
C60  0.1uF  [0402]
C1054  0.1uF  [0402]
C1055  0.1uF  [0402]
C1067  0.1uF  [0402]
C1068  0.1uF  [0402]
R124  10  [0402]
R125  10  [0402]
R126  10  [0402]
R127  10  [0402]
R128  10  [0402]
R129  10  [0402]
R130  10  [0402]
R131  4.7K  [0402]
R132  10  [0402]
R133  10  [0402]
R134  4.7K  [0402]
R135  10  [0402]
R136  10  [0402]
R137  10  [0402]
R138  10  [0402]
R139  1.5K  [0402]
R140  4.7K  [0402]
R142  4.7K  [0402]
R143  4.7K  [0402]
R144  4.7K  [0402]
R145  200  [0402]
R146  698  [0402]
R710  0  [0402]
R711  0  [0402]
R712  0  [0402]
R713  0  [0402]
R714  0  [0402]
R715  0  [0402]
R716  0  [0402]
R717  0  [0402]
R718  1K  [0402]
TP3  TP  [tp]
TP4  TP  [tp]
TP5  TP  [tp]
TP6  TP  [tp]
TP7  TP  [tp]
TP8  TP  [tp]
TP9  TP  [tp]
TP10  TP  [tp]
TP11  TP  [tp]
TP12  TP  [tp]
TP13  TP  [tp]
TP14  TP  [tp]
U80  74LVC1G66  [sc70_5]
U81  74LVC1G66  [sc70_5]
sheet 09 SerDes Mux
C61  0.01uF  [0402]
C62  0.01uF  [0402]
C63  0.01uF  [0402]
C64  0.01uF  [0402]
C65  0.01uF  [0402]
C66  0.01uF  [0402]
C67  0.01uF  [0402]
C68  0.01uF  [0402]
C69  0.01uF  [0402]
R147  4.7K  [0402]
R148  4.7K  [0402]
U16  PI3PCIE3212  [qfn_p050_d040_b450x250_20_e3x1]
U17  PI3PCIE3212  [qfn_p050_d040_b450x250_20_e3x1]
U18  PI3PCIE3212  [qfn_p050_d040_b450x250_20_e3x1]
sheet 10 USB
C70  100uF  [7343]
C71  10uF  [0805]
C72  1000pF  [0402]
C73  100uF  [7343]
C74  10uF  [0805]
C75  1000pF  [0402]
C76  10uF  [0805]
C77  0.1uF  [0402]
C78  0.1uF  [0402]
D2  CMHD3595  [sod123]
D3  CMHD3595  [sod123]
FB1  BLM21PG121SN1  [0805]
FB2  BLM21PG121SN1  [0805]
FB3  BLM21PG121SN1  [0805]
FB4  BLM21PG121SN1  [0805]
J5  USB_A_2  [con_usb_a_2]
L1  90ohm  [ind_cm_2012]
L2  90ohm  [ind_cm_2012]
Q4  IRLML6346  [sot23]
Q5  IRLML6346  [sot23]
R149  10K  [0402]
R150  10K  [0402]
R151  0  [0402]
R152  100K  [0402]
R153  100K  [0402]
R154  51.1K  [0402]
R155  0  [0402]
R156  1K  [0402]
R157  1K  [0402]
R158  51.1K  [0402]
R159  26.7K  [0402]
R160  18.2K  [0402]
R161  18.2K  [0402]
R162  0  [0402]
R163  0  [0402]
R164  0  [0402]
R165  0  [0402]
R166  10K  [0402]
R167  49.9  [0402]
R168  49.9  [0402]
R169  49.9  [0402]
U19  MAX1558H  [dfn_p050_d040_b300_10_e230x150]
U20  VBUS054B-HSF  [tvs_llp75_6l]

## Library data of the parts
C1 C2 C5-C10 C21-C23 C25-C32 C34-C36 C38-C40 C42 C43 C45 C47-C50 C55-C60 C71 C74 C76 C77 C1054 C1055 C1067 C1068 = CAP: VOLTAGE: 16V
C14 C15 C61-C69 = CAP: VOLTAGE: 25V
C17 C18 C72 C75 = CAP: VOLTAGE: 50V
C24 C33 C41 C44 C46 = CAP: VOLTAGE: 6.3V
J1 = DDR4_DIMM: MPN: 78726-1004; TYPE: CON; Vendor: Molex
R1 R2 R113 R114 R145 R146 R154 R158-R161 R166-R168 = RES: TOL: 1%
R3-R21 R23-R75 R78-R112 R115-R140 R142-R144 R147 R148 R151-R153 R155-R157 R714-R718 = RES: TOL: 5%
R22 R149 R150 R162-R165 R710-R713 = RES: BOM_IGNORE: DNP; TOL: 5%
SW1 SW2 = SWITCH_DIP_8: MPN: DHNF-08F-V; TYPE: CON; Vendor: DIPTRONICS
U2 = 74LVC16373: MPN: SN74LVC16373ADGGR; TYPE: IC; Vendor: TI
U3 = FLASH-NOR-64Mx16: TYPE: IC; Vendor: Micron
U4 = FLASH-NAND-BGA: TYPE: IC; Vendor: Micron
U5-U7 = 74LVC1G86: MPN: SN74LVC1G86DCKR; TYPE: IC; Vendor: TI
J2 = CONN_1X3: MPN: TSW-103-07-F-S; TYPE: HDR; Vendor: Samtec
J3 = SD_CONN: MPN: 54-2119-9-R; TYPE: CON; Vendor: Astron
U8 = FLASH-SERIAL-SO16: TYPE: IC; Vendor: Micron
U9 = FLASH-SERIAL-SON: BOM_IGNORE: DNP; TYPE: IC; Vendor: Micron
U10 U11 = RClamp0524J: TYPE: IC; Vendor: Sentech
D1 = LED: MPN: 0603,Green
J4 = CONN_2X8: TYPE: HDR; Vendor: Samtec
Q2 Q3 = NMOS: MPN: IRLML6346TRPBF; TYPE: MOS; Vendor: IR
TP1-TP14 = TP: TYPE: PAD
U1 = T1040: TYPE: IC; Vendor: Freescale
U12 = PCA9546A: TYPE: IC; Vendor: NXP
U13 = FXLP34P5X: TYPE: IC; Vendor: FAIRCHILD
C51 C52 = CAP: BOM_IGNORE: DNP; VOLTAGE: 50V
U80 U81 = 74LVC1G66: MPN: SN74LVC1G66DCKR; TYPE: IC; Vendor: TI
U16-U18 = PI3PCIE3212: MPN: PI3PCIE3212ZBE; TYPE: IC; Vendor: PERICOM
C70 C73 = CAP_E: TYPE: CAP; VOLTAGE: 10V
C78 = CAP: BOM_IGNORE: DNP; VOLTAGE: 16V
D2 D3 = DIODE: Vendor: Central
FB1-FB4 = BEAD: Vendor: Murata
J5 = USB_A_2: MPN: XUSB-6-7-4-3-1-3-05; TYPE: CON; Vendor: XMULTIPLE
L1 L2 = IND_CM: MPN: DLW21HN900SQ2L; TYPE: IND; Vendor: Murata
Q4 Q5 = NMOS: BOM_IGNORE: DNP; MPN: IRLML6346TRPBF; TYPE: MOS; Vendor: IR
R169 = RES: BOM_IGNORE: DNP; TOL: 1%
U19 = MAX1558H: MPN: MAX1558HETB+; TYPE: IC; Vendor: Maxim
U20 = SRV05-4: MPN: VBUS054B-HSF-GS08; TYPE: IC; Vendor: Vishay

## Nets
1V2: C1.1 C2.1 C5.1 C6.1 C7.1 C8.1 C9.1 C10.1 C14.1 C15.1 C17.1 C18.1 R1.1 R3.1 ; also on sheet 12 35
1V2_SLP: C1.2 C2.2 C5.2 C6.2 C7.2 C8.2 C9.2 C10.2 C14.2 C15.2 C17.2 C18.2 C21.1 J1.59(VDD0) J1.61(VDD1) J1.64(VDD2) J1.67(VDD3) J1.70(VDD4) J1.73(VDD5) J1.76(VDD6) J1.80(VDD7) J1.83(VDD8) J1.85(VDD9) J1.88(VDD10) J1.90(VDD11) J1.92(VDD12) J1.204(VDD13) J1.206(VDD25) J1.209(VDD14) J1.212(VDD15) J1.215(VDD16) J1.217(VDD17) J1.220(VDD18) J1.223(VDD19) J1.226(VDD20) J1.229(VDD21) J1.231(VDD22) J1.233(VDD23) J1.236(VDD24) R5.1 ; also on sheet 13 33 34 35
1V8: C29.1 C30.1 C31.1 C32.1 C33.1 C34.1 C35.1 C36.1 C38.1 C39.1 C40.1 C43.1 R6.1 R7.1 R8.1 R9.2 R10.2 R11.2 R12.2 R13.1 R14.2 R15.2 R16.1 R17.2 R18.2 R19.2 R20.2 R50.2 R51.2 R52.2 R53.2 R54.2 R55.2 R56.2 R91.2 R111.2 U2.7(VCC) U2.18(VCC) U2.31(VCC) U2.42(VCC) U3.29(VIO) U4.D3(VCC) U4.G4(VCC) U4.H8(VCC) U4.J6(VCC) U5.5(VCC) U6.5(VCC) U7.5(VCC) ; also on sheet 12 13 29 30 35
1V8_SLP: C49.1 R78.2 R79.2 R80.2 R81.2 R82.2 R83.2 R90.2 R92.2 R93.2 R94.2 R95.2 R104.1 R105.1 R106.1 R110.2 U13.1(VCC1) ; also on sheet 12 13 29 30 31 33 34 35
2V5: R718.2 ; also on sheet 12 20 21 22 23 24 25 26 35
2V5_SLP: C1067.1 C1068.1 R84.2 R85.2 R86.2 R87.2 R139.1 R140.1 U80.5(VCC) U81.5(VCC) ; also on sheet 12 19 33 35
3V3: C41.1 C42.1 C44.1 C45.1 C48.1 C61.1 C62.1 C63.1 C64.1 C65.1 C66.1 C67.1 C68.1 C69.1 J2.1 Q2.1(G) Q3.1(G) R57.2 R58.2 R59.2 R60.2 R62.2 R63.2 R74.2 R75.2 R88.2 R89.2 R98.2 R99.2 R100.2 R101.1 R102.2 R103.1 R107.1 R108.1 R109.1 U3.43(VCC) U8.2(VCC) U9.8(VCC) U12.1(A0) U12.2(A1) U12.13(A2) U12.16(VDD) U16.1(VDD) U16.6(VDD) U16.10(VDD) U17.1(VDD) U17.6(VDD) U17.10(VDD) U18.1(VDD) U18.6(VDD) U18.10(VDD) ; also on sheet 11 12 14 15 16 17 18 20 21 22 23 27 30 35
3V3_SLP: C23.1 C50.1 J1.139(SA0) J1.284(VDDSPD) R96.2 R97.2 R116.2 R117.2 R118.1 R119.1 R120.1 R121.1 R122.1 R123.1 R149.2 R150.2 R152.2 R153.2 U13.5(VCC) ; also on sheet 12 14 19 28 29 30 32 33 34 35 36
5V0_SLP: C76.1 C77.1 U19.1(INA) U19.5(INB) U20.5 ; also on sheet 32 33 35 36
5V0_USB1: C70.1 C71.1 C72.1 D3.1 FB1.2 R158.2 U19.10(OUTA)
5V0_USB2: C73.1 C74.1 C75.1 D2.1 FB3.2 R154.2 U19.6(OUTB)
GND: C22.2 C23.2 C24.2 C25.2 C26.2 C27.2 C28.2 C29.2 C30.2 C31.2 C32.2 C33.2 C34.2 C35.2 C36.2 C38.2 C39.2 C40.2 C41.2 C42.2 C43.2 C44.2 C45.2 C46.2 C47.2 C48.2 C49.2 C50.2 C51.1 C52.2 C61.2 C62.2 C63.2 C64.2 C65.2 C66.2 C67.2 C68.2 C69.2 C70.2 C71.2 C72.2 C73.2 C74.2 C75.2 C76.2 C77.2 C1067.2 C1068.2 D1.1 FB2.2 FB4.2 J1.2(GND1) J1.4(GND2) J1.6(GND3) J1.9(GND4) J1.11(GND5) J1.13(GND6) J1.15(GND7) J1.17(GND8) J1.20(GND9) J1.22(GND10) J1.24(GND11) J1.26(GND12) J1.28(GND13) J1.31(GND14) J1.33(GND15) J1.35(GND16) J1.37(GND17) J1.39(GND18) J1.42(GND19) J1.44(GND20) J1.46(GND21) J1.48(GND22) J1.50(GND23) J1.53(GND24) J1.55(GND25) J1.57(GND26) J1.94(GND27) J1.96(GND0) J1.98(GND28) J1.101(GND29) J1.103(GND30) J1.105(GND31) J1.107(GND32) J1.109(GND33) J1.112(GND34) J1.114(GND35) J1.116(GND36) J1.118(GND37) J1.120(GND38) J1.123(GND39) J1.125(GND40) J1.127(GND41) J1.129(GND42) J1.131(GND43) J1.134(GND44) J1.136(GND45) J1.138(GND46) J1.140(SA1) J1.147(GND47) J1.149(GND48) J1.151(GND49) J1.154(GND50) J1.156(GND51) J1.158(GND52) J1.160(GND53) J1.162(GND54) J1.165(GND55) J1.167(GND56) J1.169(GND57) J1.171(GND58) J1.173(GND59) J1.176(GND60) J1.178(GND61) J1.180(GND62) J1.182(GND63) J1.184(GND64) J1.187(GND65) J1.189(GND66) J1.191(GND67) J1.193(GND68) J1.195(GND69) J1.198(GND70) J1.200(GND71) J1.202(GND72) J1.238(SA2) J1.239(GND73) J1.241(GND74) J1.243(GND75) J1.246(GND76) J1.248(GND77) J1.250(GND78) J1.252(GND79) J1.254(GND80) J1.257(GND81) J1.259(GND82) J1.261(GND83) J1.263(GND84) J1.265(GND85) J1.268(GND86) J1.270(GND87) J1.272(GND88) J1.274(GND89) J1.276(GND90) J1.279(GND91) J1.281(GND92) J1.283(GND93) J3.3(VSS) J3.6(VSS) J3.12(COM1) J3.13(COM2) J4.12 J4.16 Q4.2(S) Q5.2(S) R2.1 R4.1 R22.1 R31.2 R33.2 R35.2 R37.2 R38.2 R39.2 R40.2 R41.2 R42.2 R43.2 R44.2 R45.2 R46.2 R47.2 R48.2 R49.2 R113.1 R114.1 R115.1 R131.1 R134.2 R142.1 R143.1 R144.1 R147.1 R148.1 R156.1 R157.1 R159.1 R160.1 R161.1 R166.1 R167.1 R168.1 R169.1 U1.AC1(EC1_COL) U1.AC2(EC1_RX_ER) U1.AG10(SD1_RX0_N) U1.AH10(SD1_RX0_P) U2.1(~{OE1}) U2.4(GND) U2.10(GND) U2.15(GND) U2.21(GND) U2.24(~{OE2}) U2.26(2D8) U2.27(2D7) U2.28(GND) U2.29(2D6) U2.30(2D5) U2.32(2D4) U2.34(GND) U2.39(GND) U2.45(GND) U3.33(GND) U3.52(GND) U4.C5(VSS) U4.F7(VSS) U4.K3(VSS) U4.K8(VSS) U5.3(GND) U6.3(GND) U7.3(GND) U8.10(GND) U9.4(GND) U9.9(EPAD) U10.9 U11.9 U12.8(VSS) U13.3(GND) U16.2(PD) U16.5(GND) U16.11(GND) U16.20(GND) U16.21(EPAD) U17.2(PD) U17.5(GND) U17.11(GND) U17.20(GND) U17.21(EPAD) U18.2(PD) U18.5(GND) U18.11(GND) U18.20(GND) U18.21(EPAD) U19.8(GND) U19.11(EPAD) U20.2 U80.3(GND) U81.3(GND) ; also on sheet 11 12 13 14 15 16 17 18 19 20 21 22 23 24 25 26 27 28 29 30 31 32 33 34 35 36 37
SVDD: R145.1 ; also on sheet 12
VDD_SD: C46.1 C47.1 J2.2 J3.4(VDD)
ASLEEP: R110.1 U1.B2(ASLEEP) U13.2(A)
AURORA_RX_N: U18.19(B0+) ; also on sheet 28
AURORA_RX_P: U18.18(B0-) ; also on sheet 28
AURORA_TX_N: U18.17(B1+) ; also on sheet 28
AURORA_TX_P: U18.16(B1-) ; also on sheet 28
CFG_VBANK0: U7.2(I1) ; also on sheet 29
CFG_VBANK1: U6.2(I1) ; also on sheet 29
CFG_VBANK2: U5.2(I1) ; also on sheet 29
CKSTP_OUT_N: R111.1 U1.F18(CKSTP_OUT_B) ; also on sheet 29
COP_CKSTP_OUT_N: J4.15 ; also on sheet 29
COP_HRESET_N: J4.13 R123.2 ; also on sheet 29
COP_SRESET_N: J4.11 R122.2 ; also on sheet 29
COP_TCK: J4.7 R120.2 ; also on sheet 29
COP_TDI: J4.3 R118.2 ; also on sheet 29
COP_TDO: J4.1 ; also on sheet 29
COP_TMS: J4.9 R121.2 ; also on sheet 29
COP_TRST_N: J4.4 R117.1 ; also on sheet 29
CPLD_INT1_N: R78.1 U1.F7(IRQ00) ; also on sheet 29
CPLD_INT2_N: R79.1 U1.D3(IRQ01) ; also on sheet 29
DDR_DQ0: J1.5(DQ0) U1.C21(D1_MDQ00)
DDR_DQ1: J1.150(DQ1) U1.A22(D1_MDQ01)
DDR_DQ2: J1.12(DQ2) U1.A26(D1_MDQ02)
DDR_DQ3: J1.157(DQ3) U1.B26(D1_MDQ03)
DDR_DQ4: J1.3(DQ4) U1.B21(D1_MDQ04)
DDR_DQ5: J1.148(DQ5) U1.A21(D1_MDQ05)
DDR_DQ6: J1.10(DQ6) U1.B24(D1_MDQ06)
DDR_DQ7: J1.155(DQ7) U1.A25(D1_MDQ07)
DDR_DQ8: J1.16(DQ8) U1.C23(D1_MDQ08)
DDR_DQ9: J1.161(DQ9) U1.C24(D1_MDQ09)
DDR_DQ10: J1.23(DQ10) U1.F25(D1_MDQ10)
DDR_DQ11: J1.168(DQ11) U1.F26(D1_MDQ11)
DDR_DQ12: J1.14(DQ12) U1.D22(D1_MDQ12)
DDR_DQ13: J1.159(DQ13) U1.D23(D1_MDQ13)
DDR_DQ14: J1.21(DQ14) U1.B27(D1_MDQ14)
DDR_DQ15: J1.166(DQ15) U1.E25(D1_MDQ15)
DDR_DQ16: J1.27(DQ16) U1.E23(D1_MDQ16)
DDR_DQ17: J1.172(DQ17) U1.E24(D1_MDQ17)
DDR_DQ18: J1.34(DQ18) U1.J23(D1_MDQ18)
DDR_DQ19: J1.179(DQ19) U1.K23(D1_MDQ19)
DDR_DQ20: J1.25(DQ20) U1.F22(D1_MDQ20)
DDR_DQ21: J1.170(DQ21) U1.H22(D1_MDQ21)
DDR_DQ22: J1.32(DQ22) U1.H23(D1_MDQ22)
DDR_DQ23: J1.177(DQ23) U1.J24(D1_MDQ23)
DDR_DQ24: J1.38(DQ24) U1.H26(D1_MDQ24)
DDR_DQ25: J1.183(DQ25) U1.J25(D1_MDQ25)
DDR_DQ26: J1.45(DQ26) U1.P26(D1_MDQ26)
DDR_DQ27: J1.190(DQ27) U1.N25(D1_MDQ27)
DDR_DQ28: J1.36(DQ28) U1.G25(D1_MDQ28)
DDR_DQ29: J1.181(DQ29) U1.H25(D1_MDQ29)
DDR_DQ30: J1.43(DQ30) U1.M26(D1_MDQ30)
DDR_DQ31: J1.188(DQ31) U1.M25(D1_MDQ31)
DDR_DQ32: J1.97(DQ32) U1.T25(D1_MDQ32)
DDR_DQ33: J1.242(DQ33) U1.U25(D1_MDQ33)
DDR_DQ34: J1.104(DQ34) U1.AA26(D1_MDQ34)
DDR_DQ35: J1.249(DQ35) U1.AA25(D1_MDQ35)
DDR_DQ36: J1.95(DQ36) U1.P25(D1_MDQ36)
DDR_DQ37: J1.240(DQ37) U1.R25(D1_MDQ37)
DDR_DQ38: J1.102(DQ38) U1.W26(D1_MDQ38)
DDR_DQ39: J1.247(DQ39) U1.Y25(D1_MDQ39)
DDR_DQ40: J1.108(DQ40) U1.V24(D1_MDQ40)
DDR_DQ41: J1.253(DQ41) U1.W23(D1_MDQ41)
DDR_DQ42: J1.115(DQ42) U1.AA22(D1_MDQ42)
DDR_DQ43: J1.260(DQ43) U1.AC22(D1_MDQ43)
DDR_DQ44: J1.106(DQ44) U1.W22(D1_MDQ44)
DDR_DQ45: J1.251(DQ45) U1.V23(D1_MDQ45)
DDR_DQ46: J1.113(DQ46) U1.AB24(D1_MDQ46)
DDR_DQ47: J1.258(DQ47) U1.AB23(D1_MDQ47)
DDR_DQ48: J1.119(DQ48) U1.AD26(D1_MDQ48)
DDR_DQ49: J1.264(DQ49) U1.AD25(D1_MDQ49)
DDR_DQ50: J1.126(DQ50) U1.AD23(D1_MDQ50)
DDR_DQ51: J1.271(DQ51) U1.AE22(D1_MDQ51)
DDR_DQ52: J1.117(DQ52) U1.AB25(D1_MDQ52)
DDR_DQ53: J1.262(DQ53) U1.AC25(D1_MDQ53)
DDR_DQ54: J1.124(DQ54) U1.AC23(D1_MDQ54)
DDR_DQ55: J1.269(DQ55) U1.AE23(D1_MDQ55)
DDR_DQ56: J1.130(DQ56) U1.AG25(D1_MDQ56)
DDR_DQ57: J1.275(DQ57) U1.AH25(D1_MDQ57)
DDR_DQ58: J1.137(DQ58) U1.AH22(D1_MDQ58)
DDR_DQ59: J1.282(DQ59) U1.AF22(D1_MDQ59)
DDR_DQ60: J1.128(DQ60) U1.AF26(D1_MDQ60)
DDR_DQ61: J1.273(DQ61) U1.AH26(D1_MDQ61)
DDR_DQ62: J1.135(DQ62) U1.AH23(D1_MDQ62)
DDR_DQ63: J1.280(DQ63) U1.AF23(D1_MDQ63)
DDR_ECC0: J1.49(CB0) U1.L24(D1_MECC0)
DDR_ECC1: J1.194(CB1/NC15) U1.N23(D1_MECC1)
DDR_ECC2: J1.56(CB2) U1.T23(D1_MECC2)
DDR_ECC3: J1.201(CB3/NC17) U1.U23(D1_MECC3)
DDR_ECC4: J1.47(CB4) U1.L23(D1_MECC4)
DDR_ECC5: J1.192(CB5/NC14) U1.M23(D1_MECC5)
DDR_ECC6: J1.54(CB6) U1.R24(D1_MECC6)
DDR_ECC7: J1.199(CB7/NC16) U1.T24(D1_MECC7)
DDR_MA0: J1.79(A0) U1.V28(D1_MA00)
DDR_MA1: J1.72(A1) U1.N28(D1_MA01)
DDR_MA2: J1.216(A2) U1.N27(D1_MA02)
DDR_MA3: J1.71(A3) U1.M28(D1_MA03)
DDR_MA4: J1.214(A4) U1.L27(D1_MA04)
DDR_MA5: J1.213(A5) U1.L28(D1_MA05)
DDR_MA6: J1.69(A6) U1.K28(D1_MA06)
DDR_MA7: J1.211(A7) U1.J28(D1_MA07)
DDR_MA8: J1.68(A8) U1.J27(D1_MA08)
DDR_MA9: J1.66(A9) U1.G27(D1_MA09)
DDR_MA10: J1.225(A10/AP) U1.Y27(D1_MA10)
DDR_MA11: J1.210(A11) U1.H28(D1_MA11)
DDR_MA12: J1.65(A12/~{BC}) U1.G28(D1_MA12)
DDR_MA13: J1.232(A13) U1.AE28(D1_MA13)
DDR_MA14: J1.207(BG1) U1.E27(D1_MA14)
DDR_MA15: J1.62(~{ACT}) U1.D28(D1_MA15)
DDR_MAPAR_ERR: J1.208(~{ALERT}) R3.2 U1.F28(D1_MAPAR_ERR_B)
DDR_MAPAR_OUT: J1.222(PARITY) U1.V27(D1_MAPAR_OUT)
DDR_MBA0: J1.81(BA0) U1.Y28(D1_MBA0)
DDR_MBA1: J1.224(BA1) U1.W28(D1_MBA1)
DDR_MBA2: J1.63(BG0) U1.E28(D1_MBA2)
DDR_MCAS_N: J1.86(~{CAS}/A15) U1.AC28(D1_MCAS_B)
DDR_MCK0_N: J1.75(CK0_N) U1.T28(D1_MCK0_B)
DDR_MCK0_P: J1.74(CK0_P) U1.T27(D1_MCK0)
DDR_MCK1_N: J1.219(CK1_N) U1.R28(D1_MCK1_B)
DDR_MCK1_P: J1.218(CK1_P) U1.R27(D1_MCK1)
DDR_MCKE0: J1.60(CKE0) U1.C27(D1_MCKE0) ; also on sheet 35
DDR_MCKE1: J1.203(CKE1/NC18) U1.C28(D1_MCKE1) ; also on sheet 35
DDR_MCS0_N: J1.84(~{S0}) U1.AB28(D1_MCS0_B)
DDR_MCS1_N: J1.89(~{CS1}/NC7) U1.AC27(D1_MCS1_B)
DDR_MCS2_N: J1.93(~{CS2}/NC8) U1.AG27(D1_MCS2_B)
DDR_MCS3_N: J1.237(~{CS3}/C1/NC22) U1.AF28(D1_MCS3_B)
DDR_MDM0: J1.7(DQS9_P/DM0) U1.B22(D1_MDM0)
DDR_MDM1: J1.18(DQS10_P/DM1) U1.C25(D1_MDM1)
DDR_MDM2: J1.29(DQS11_P/DM2) U1.F23(D1_MDM2)
DDR_MDM3: J1.40(DQS12_P/DM3) U1.K26(D1_MDM3)
DDR_MDM4: J1.99(DQS13_P/DM4) U1.U26(D1_MDM4)
DDR_MDM5: J1.110(DQS14_P/DM5) U1.Y24(D1_MDM5)
DDR_MDM6: J1.121(DQS15_P/DM6) U1.AD24(D1_MDM6)
DDR_MDM7: J1.132(DQS16_P/DM7) U1.AF24(D1_MDM7)
DDR_MDM8: J1.51(DQS17_P/DM8) U1.N24(D1_MDM8)
DDR_MDQS0_N: J1.152(DQS0_N) U1.A23(D1_MDQS0_B)
DDR_MDQS0_P: J1.153(DQS0_P) U1.A24(D1_MDQS0)
DDR_MDQS1_N: J1.163(DQS1_N) U1.D25(D1_MDQS1_B)
DDR_MDQS1_P: J1.164(DQS1_P) U1.D26(D1_MDQS1)
DDR_MDQS2_N: J1.174(DQS2_N) U1.G23(D1_MDQS2_B)
DDR_MDQS2_P: J1.175(DQS2_P) U1.G24(D1_MDQS2)
DDR_MDQS3_N: J1.185(DQS3_N) U1.K25(D1_MDQS3_B)
DDR_MDQS3_P: J1.186(DQS3_P) U1.L25(D1_MDQS3)
DDR_MDQS4_N: J1.244(DQS4_N) U1.V25(D1_MDQS4_B)
DDR_MDQS4_P: J1.245(DQS4_P) U1.W25(D1_MDQS4)
DDR_MDQS5_N: J1.255(DQS5_N) U1.Y23(D1_MDQS5_B)
DDR_MDQS5_P: J1.256(DQS5_P) U1.AA23(D1_MDQS5)
DDR_MDQS6_N: J1.266(DQS6_N) U1.AF25(D1_MDQS6_B)
DDR_MDQS6_P: J1.267(DQS6_P) U1.AE25(D1_MDQS6)
DDR_MDQS7_N: J1.277(DQS7_N) U1.AH24(D1_MDQS7_B)
DDR_MDQS7_P: J1.278(DQS7_P) U1.AG24(D1_MDQS7)
DDR_MDQS8_N: J1.196(DQS8_N) U1.P23(D1_MDQS8_B)
DDR_MDQS8_P: J1.197(DQS8_P) U1.R23(D1_MDQS8)
DDR_MODT0: J1.87(ODT0) U1.AD28(D1_MODT0)
DDR_MODT1: J1.91(ODT1) U1.AE27(D1_MODT1)
DDR_MRAS_N: J1.82(~{RAS}/A16) U1.AA28(D1_MRAS_B)
DDR_MWE_N: J1.228(~{WE}/A14) U1.AB27(D1_MWE_B)
DDR_REFCLK: U1.J21(DDRCLK) ; also on sheet 30
DDR_RST_N: J1.58(~{RESET}) R5.2 ; also on sheet 29
DIU_HSYNC: U1.AA3(IIC4_SCL) ; also on sheet 11
DIU_VSYNC: U1.AB3(IIC4_SDA) ; also on sheet 11
EARTH: J5.9 J5.10 J5.11 J5.12 ; also on sheet 14 16 19 20 21 22 23 26 37
EC1_GTXCLK: R132.1 ; also on sheet 19
EC1_INT_N: R84.1 U1.AB4(IRQ06) ; also on sheet 19
EC1_PME_N: R85.1 U1.AD5(IRQ07) ; also on sheet 19
EC1_REFCLK: U1.AG3(EC1_GTX_CLK125) ; also on sheet 19
EC1_RXCLK: R710.1 R714.1 ; also on sheet 19
EC1_RXCTL: U1.AG2(EC1_RX_CTL) ; also on sheet 19
EC1_RXD0: U1.AF2(EC1_RXD0) ; also on sheet 19
EC1_RXD1: U1.AF1(EC1_RXD1) ; also on sheet 19
EC1_RXD2: U1.AE1(EC1_RXD2) ; also on sheet 19
EC1_RXD3: U1.AD2(EC1_RXD3) ; also on sheet 19
EC1_TXCTL: R135.1 ; also on sheet 19
EC1_TXD0: R133.1 ; also on sheet 19
EC1_TXD1: R125.1 ; also on sheet 19
EC1_TXD2: R127.1 ; also on sheet 19
EC1_TXD3: R129.1 ; also on sheet 19
EC2_GTXCLK: R137.2 ; also on sheet 20
EC2_INT_N: R82.1 U1.D4(IRQ04) ; also on sheet 20
EC2_PME_N: R83.1 U1.D5(IRQ05) ; also on sheet 20
EC2_REFCLK: U1.AC6(EC2_GTX_CLK125) ; also on sheet 20
EC2_RXCLK: R713.2 R717.2 ; also on sheet 20
EC2_RXCTL: U1.AG8(EC2_RX_CTL) ; also on sheet 20
EC2_RXD0: U1.AH8(EC2_RXD0) ; also on sheet 20
EC2_RXD1: U1.AG7(EC2_RXD1) ; also on sheet 20
EC2_RXD2: U1.AH7(EC2_RXD2) ; also on sheet 20
EC2_RXD3: U1.AH6(EC2_RXD3) ; also on sheet 20
EC2_TXCTL: R136.2 ; also on sheet 20
EC2_TXD0: R124.2 ; also on sheet 20
EC2_TXD1: R126.2 ; also on sheet 20
EC2_TXD2: R128.2 ; also on sheet 20
EC2_TXD3: R130.2 ; also on sheet 20
EMI1_MDC: U80.2(B) ; also on sheet 20 21 22 23 24 25
EMI1_MDC_SLP: R138.1 R140.2 U80.1(A) ; also on sheet 19
EMI1_MDIO: U81.2(B) ; also on sheet 20 21 22 23 24 25
EMI1_MDIO_SLP: R139.2 U1.AH4(EMI1_MDIO) U81.1(A) ; also on sheet 19
EVDD: J2.3 R68.2 R69.2 R70.2 R71.2 R72.2 R73.2 ; also on sheet 12 35
EVT0_N: U1.D6(EVT0_B) ; also on sheet 29
EVT1_N: U1.C4(EVT1_B) ; also on sheet 29
EVT4_N: U1.C3(EVT4_B) ; also on sheet 29
EVT_BRD_ISO: R90.1 U1.A3(IRQ_OUT_B) ; also on sheet 29
EVT_PWR_EN: R94.1 U1.C1(EVT2_B) ; also on sheet 29
EVT_PWR_OK: R95.1 U1.C2(EVT3_B) ; also on sheet 29
GPIO_CKE_ISO: R87.1 U1.AC5(IRQ09) ; also on sheet 29
HRESET_N: R105.2 U1.E8(HRESET_B) ; also on sheet 29
I2C1_SCL: Q2.2(S) R99.1 U1.W1(IIC1_SCL) ; also on sheet 14 16 17
I2C1_SCL_SLP: J1.141(SCL) Q2.3(D) R97.1 ; also on sheet 14 31 32
I2C1_SDA: Q3.2(S) R98.1 U1.V1(IIC1_SDA) ; also on sheet 14 16 17
I2C1_SDA_SLP: J1.285(SDA) Q3.3(D) R96.1 ; also on sheet 14 31 32
I2C2_HDMI_SCL: U12.10(SC2) ; also on sheet 16
I2C2_HDMI_SDA: U12.9(SD2) ; also on sheet 16
I2C2_MPEX1_SCL: U12.5(SC0) ; also on sheet 27
I2C2_MPEX1_SDA: U12.4(SD0) ; also on sheet 27
I2C2_MPEX2_SCL: U12.7(SC1) ; also on sheet 27
I2C2_MPEX2_SDA: U12.6(SD1) ; also on sheet 27
I2C2_PEX_SCL: U12.12(SC3) ; also on sheet 27
I2C2_PEX_SDA: U12.11(SD3) ; also on sheet 27
IFC_A5: R23.2 U7.1(I0)
IFC_A6: R24.2 U6.1(I0)
IFC_A7: R25.2 U5.1(I0)
IFC_A8: R26.2 U3.2(A22)
IFC_A9: R27.2 U3.15(A21)
IFC_A10: R28.2 U3.12(A20)
IFC_A11: R29.2 U3.11(A19)
IFC_A12: R30.2 U3.18(A18)
IFC_A13: R32.2 U3.19(A17)
IFC_A14: R34.2 U3.54(A16)
IFC_A15: R36.2 U3.3(A15)
IFC_A16: R6.2 SW2.5 U1.C5(IFC_A16) U3.4(A14) ; also on sheet 29
IFC_A17: R7.2 SW2.6 U1.C6(IFC_A17) U3.5(A13) ; also on sheet 29
IFC_A18: R8.2 SW2.3 U1.D7(IFC_A18) U3.6(A12)
IFC_A19: R13.2 SW2.4 U1.C7(IFC_A19) U3.7(A11)
IFC_A20: R16.2 R22.2 U1.D8(IFC_A20) U3.8(A10)
IFC_A21: SW2.7 U1.C8(IFC_A21) U3.9(A9)
IFC_A22: U1.D9(IFC_A22) U3.10(A8)
IFC_A23: U1.C9(IFC_A23) U3.20(A7)
IFC_A24: U1.D10(IFC_A24) U3.21(A6)
IFC_A25: U1.C10(IFC_A25) U3.22(A5)
IFC_A26: U1.E11(IFC_A26) U3.23(A4)
IFC_A27: U1.C11(IFC_A27) U3.24(A3) ; also on sheet 29
IFC_A28: U1.D11(IFC_A28) U3.25(A2) ; also on sheet 29
IFC_A29: U1.C12(IFC_A29) U3.26(A1) ; also on sheet 29
IFC_A30: U1.D12(IFC_A30) U3.31(A0) ; also on sheet 29
IFC_A31: U1.E12(IFC_A31) ; also on sheet 29
IFC_AD0: U1.A4(IFC_AD00) U3.51(DQ15/A-1) U4.J8(I/O7) ; also on sheet 29
IFC_AD1: U1.B5(IFC_AD01) U3.49(DQ14) U4.K7(I/O6) ; also on sheet 29
IFC_AD2: U1.A5(IFC_AD02) U3.47(DQ13) U4.J7(I/O5) ; also on sheet 29
IFC_AD3: U1.B6(IFC_AD03) U3.45(DQ12) U4.K6(I/O4) ; also on sheet 29
IFC_AD4: U1.A6(IFC_AD04) U3.42(DQ11) U4.K5(I/O3) ; also on sheet 29
IFC_AD5: U1.A7(IFC_AD05) U2.47(1D1) U3.40(DQ10) U4.K4(I/O2) ; also on sheet 29
IFC_AD6: U1.B8(IFC_AD06) U2.46(1D2) U3.38(DQ9) U4.J4(I/O1) ; also on sheet 29
IFC_AD7: U1.A8(IFC_AD07) U2.44(1D3) U3.36(DQ8) U4.H4(I/O0) ; also on sheet 29
IFC_AD8: SW1.1 U1.B9(IFC_AD08) U2.43(1D4) U3.50(DQ7) ; also on sheet 29
IFC_AD9: SW1.2 U1.A9(IFC_AD09) U2.41(1D5) U3.48(DQ6) ; also on sheet 29
IFC_AD10: SW1.3 U1.A10(IFC_AD10) U2.40(1D6) U3.46(DQ5) ; also on sheet 29
IFC_AD11: SW1.4 U1.B11(IFC_AD11) U2.38(1D7) U3.44(DQ4) ; also on sheet 29
IFC_AD12: SW1.5 U1.A11(IFC_AD12) U2.37(1D8) U3.41(DQ3) ; also on sheet 29
IFC_AD13: SW1.6 U1.B12(IFC_AD13) U2.36(2D1) U3.39(DQ2) ; also on sheet 29
IFC_AD14: SW1.7 U1.A12(IFC_AD14) U2.35(2D2) U3.37(DQ1) ; also on sheet 29
IFC_AD15: SW1.8 U1.A13(IFC_AD15) U2.33(2D3) U3.35(DQ0) ; also on sheet 29
IFC_AVD: R17.1 SW2.8 U1.D17(IFC_AVD) U2.25(LE2) U2.48(LE1) U4.C4(ALE)
IFC_CLE: SW2.1 U1.F16(IFC_CLE) U4.D5(CLE) ; also on sheet 29
IFC_CLK: R21.2 ; also on sheet 29
IFC_CS0_N: R12.1 U1.C13(IFC_CS0_B) ; also on sheet 29
IFC_CS1_N: R15.1 U1.E15(IFC_CS1_B) ; also on sheet 29
IFC_CS2_N: R11.1 U1.D16(IFC_CS2_B) ; also on sheet 29
IFC_NDWE_N: U1.D14(IFC_NDDDR_CLK) U4.C7(~{WE})
IFC_OE_N: R19.1 U1.D15(IFC_OE_B) U3.34(~{OE}) U4.D4(~{RE}) ; also on sheet 29
IFC_RB0_N: R10.1 U1.B15(IFC_RB0_B) ; also on sheet 29
IFC_RB1_N: R9.1 U1.A15(IFC_RB1_B) ; also on sheet 29
IFC_TE: SW2.2 U1.B14(IFC_TE)
IFC_VA5: U3.55(A25) U7.4(O)
IFC_VA6: U3.56(A24) U6.4(O)
IFC_VA7: U3.1(A23) U5.4(O)
IFC_WE_N: R20.1 U1.D13(IFC_WE0_B) U3.13(~{WE}) ; also on sheet 29
IFC_WP_N: R18.1 U1.F17(IFC_WP0_B) U4.C3(~{WP}) ; also on sheet 29
JTAG_TCK: U1.E18(TCK) ; also on sheet 29
JTAG_TDI: U1.A18(TDI) ; also on sheet 29
JTAG_TDO: U1.C18(TDO) ; also on sheet 29
JTAG_TMS: U1.B18(TMS) ; also on sheet 29
JTAG_TRST_N: U1.D19(TRST_B) ; also on sheet 29
MPEX1_RX_N: U1.AG17(SD1_RX5_N) ; also on sheet 27
MPEX1_RX_P: U1.AH17(SD1_RX5_P) ; also on sheet 27
MPEX1_TX_N: U1.AE17(SD1_TX5_N) ; also on sheet 27
MPEX1_TX_P: U1.AD17(SD1_TX5_P) ; also on sheet 27
MPEX2_RX_N: U1.AG19(SD1_RX6_N) ; also on sheet 27
MPEX2_RX_P: U1.AH19(SD1_RX6_P) ; also on sheet 27
MPEX2_TX_N: U1.AE19(SD1_TX6_N) ; also on sheet 27
MPEX2_TX_P: U1.AD19(SD1_TX6_P) ; also on sheet 27
MVREF: C21.2 C22.1 J1.146(VREFCA) ; also on sheet 34
NAND_CS_N: R53.1 U4.C6(~{CE}) ; also on sheet 29
NAND_RB_N: R56.1 U4.C8(R/~{B}) ; also on sheet 29
NC1_12V: J1.1(NC1_12V)
NC13_12V: J1.145(NC13_12V)
NOR_CS_N: R50.1 U3.32(~{CE}) ; also on sheet 29
NOR_RB_N: R54.1 U3.17(RDY/~{BUSY}) ; also on sheet 29
NOR_RST_N: R55.1 U3.14(~{RESET}) ; also on sheet 29
PEX_RX_N: U18.15(C0+) ; also on sheet 27
PEX_RX_P: U18.14(C0-) ; also on sheet 27
PEX_SEL: R148.2 U18.9(SEL) ; also on sheet 29
PEX_TX_N: U18.13(C1+) ; also on sheet 27
PEX_TX_P: U18.12(C1-) ; also on sheet 27
PORESET_N: R104.2 U1.F13(PORESET_B) ; also on sheet 29
QSG_SEL_N: R147.2 U16.9(SEL) U17.9(SEL) ; also on sheet 29
QSGMII1_RX_N: U16.19(B0+) ; also on sheet 24
QSGMII1_RX_P: U16.18(B0-) ; also on sheet 24
QSGMII1_TX_N: U16.17(B1+) ; also on sheet 24
QSGMII1_TX_P: U16.16(B1-) ; also on sheet 24
QSGMII2_RX_N: U17.19(B0+) ; also on sheet 25
QSGMII2_RX_P: U17.18(B0-) ; also on sheet 25
QSGMII2_TX_N: U17.17(B1+) ; also on sheet 25
QSGMII2_TX_P: U17.16(B1-) ; also on sheet 25
RESET_REQ_N: R106.2 U1.B3(RESET_REQ_B) ; also on sheet 29
RTC_INT_N: R80.1 U1.E9(IRQ02) ; also on sheet 14
SATA_RX_N: U1.AG20(SD1_RX7_N) ; also on sheet 27
SATA_RX_P: U1.AH20(SD1_RX7_P) ; also on sheet 27
SATA_TX_N: U1.AE20(SD1_TX7_N) ; also on sheet 27
SATA_TX_P: U1.AD20(SD1_TX7_P) ; also on sheet 27
SD_REFCLK1_N: U1.AA14(SD1_REF_CLK1_N) ; also on sheet 31
SD_REFCLK1_P: U1.AB14(SD1_REF_CLK1_P) ; also on sheet 31
SD_REFCLK2_N: C1055.2 ; also on sheet 30
SD_REFCLK2_P: C1054.2 ; also on sheet 30
SD_RX2_N: C55.1 U16.3(A0+)
SD_RX2_P: C58.1 U16.4(A0-)
SD_RX3_N: C60.1 U17.3(A0+)
SD_RX3_P: C59.1 U17.4(A0-)
SD_RX4_N: U1.AG16(SD1_RX4_N) U18.3(A0+)
SD_RX4_P: U1.AH16(SD1_RX4_P) U18.4(A0-)
SD_TX2_N: U1.AE13(SD1_TX2_N) U16.7(A1+)
SD_TX2_P: U1.AD13(SD1_TX2_P) U16.8(A1-)
SD_TX3_N: U1.AE14(SD1_TX3_N) U17.7(A1+)
SD_TX3_P: U1.AD14(SD1_TX3_P) U17.8(A1-)
SD_TX4_N: U1.AE16(SD1_TX4_N) U18.7(A1+)
SD_TX4_P: U1.AD16(SD1_TX4_P) U18.8(A1-)
SDHC_CD_N: J3.10(~{INSERT}) R74.1 U1.L5(SDHC_CD_B) U10.4 U10.5
SDHC_CLK: J3.5(CLK/SCLK) R67.2 R72.1 U11.1 U11.8
SDHC_CMD: J3.2(CMD/DIN) R73.1 U1.K3(SDHC_CMD) U10.3 U10.6
SDHC_DAT0: J3.7(D0/DOUT) R69.1 U1.L2(SDHC_DAT0) U11.2 U11.7
SDHC_DAT1: J3.8(D1/RSV) R68.1 U1.K4(SDHC_DAT1) U11.3 U11.6
SDHC_DAT2: J3.9(D2/RSV) R70.1 U1.L3(SDHC_DAT2) U10.1 U10.8
SDHC_DAT3: J3.1(D3/~{CS}) R71.1 U1.L1(SDHC_DAT3) U10.2 U10.7
SDHC_VS: R81.1 U1.D1(IRQ03) ; also on sheet 29
SDHC_WP: J3.11(~{PROTECT}) R75.1 U1.M5(SDHC_WP) U11.4 U11.5
SG_INT_N: R86.1 U1.AB1(IRQ08) ; also on sheet 21
SGMII1_RX_N: U16.15(C0+) ; also on sheet 22
SGMII1_RX_P: U16.14(C0-) ; also on sheet 22
SGMII1_TX_N: U16.13(C1+) ; also on sheet 22
SGMII1_TX_P: U16.12(C1-) ; also on sheet 22
SGMII2_RX_N: U17.15(C0+) ; also on sheet 23
SGMII2_RX_P: U17.14(C0-) ; also on sheet 23
SGMII2_TX_N: U17.13(C1+) ; also on sheet 23
SGMII2_TX_P: U17.12(C1-) ; also on sheet 23
SGMII_RX_N: C57.1 ; also on sheet 21
SGMII_RX_P: C56.1 ; also on sheet 21
SGMII_TX_N: U1.AE11(SD1_TX1_N) ; also on sheet 21
SGMII_TX_P: U1.AD11(SD1_TX1_P) ; also on sheet 21
SPI_CLK: R65.2 R66.1 ; also on sheet 15
SPI_CS0_N: R60.1 U1.M1(SPI_CS0_B) U8.7(~{CS}) U9.1(~{CS})
SPI_MISO: R58.1 R61.1 U1.P1(SPI_MISO) ; also on sheet 15
SPI_MOSI: R64.1 U1.P2(SPI_MOSI) ; also on sheet 15
SYS_REFCLK: U1.G15(SYSCLK) ; also on sheet 30
SYS_REFCLK_N: U1.F14(DIFF_SYSCLK_B) ; also on sheet 31
SYS_REFCLK_P: U1.G14(DIFF_SYSCLK) ; also on sheet 31
TDMR_SPI_CS0_N: R63.1 U1.M2(SPI_CS1_B) ; also on sheet 15
TDMR_SPI_CS1_N: R62.1 U1.M3(SPI_CS2_B) ; also on sheet 15
TEMP_DIODE_N: U1.G21(TD1_CATHODE) ; also on sheet 14
TEMP_DIODE_P: U1.E21(TD1_ANODE) ; also on sheet 14
TEST_SEL_N: R92.1 U1.G8(TEST_SEL_B) ; also on sheet 29
UART1_CTS_N: U1.Y2(UART1_CTS_B) ; also on sheet 14
UART1_RTS_N: U1.Y1(UART1_RTS_B) ; also on sheet 14
UART1_RXD: U1.AA1(UART1_SIN) ; also on sheet 14
UART1_TXD: U1.AA2(UART1_SOUT) ; also on sheet 14
UART2_CTS_N: U1.Y4(UART2_CTS_B) ; also on sheet 14
UART2_RTS_N: U1.V4(UART2_RTS_B) ; also on sheet 14
UART2_RXD: U1.W4(UART2_SIN) ; also on sheet 14
UART2_TXD: U1.AA4(UART2_SOUT) ; also on sheet 14
USB1_DM: J5.6 L1.2 R163.2 U20.6
USB1_DP: J5.7 L1.3 R162.2 U20.4
USB1_FLG_N: Q4.1(G) R151.2 R153.1 U19.9(~{FLTA})
USB1_PWREN: R157.2 U1.F6(USB1_DRVVBUS) U19.2(ONA)
USB1_VBUS: FB1.1 J5.5
USB1_VBUSCLMP: D3.2 R158.1 R161.2 U1.E4(USB1_VBUSCLMP)
USB2_DM: J5.2 L2.2 R165.2 U20.3
USB2_DP: J5.3 L2.3 R164.2 U20.1
USB2_FLG_N: Q5.1(G) R152.1 R155.2 U19.7(~{FLTB})
USB2_PWREN: R156.2 U1.J5(USB2_DRVVBUS) U19.4(ONB)
USB2_VBUS: FB3.1 J5.1
USB2_VBUSCLMP: D2.2 R154.1 R160.2 U1.J4(USB2_VBUSCLMP)
USB_REFCLK: U1.F8(USBCLK) ; also on sheet 30
VPP: J1.142(VPP1) J1.143(VPP2) J1.286(VPP3) J1.287(VPP4) J1.288(VPP5) ; also on sheet 34
VTT: C24.1 C25.1 C26.1 C27.1 C28.1 J1.77(VTT1) J1.221(VTT2) ; also on sheet 34
XVDD: R146.1 ; also on sheet 12
N16747459: R1.2 U1.U28(D1_MDIC1)
N16747463: R2.2 U1.P28(D1_MDIC0)
N16770065: R4.2 U1.F20(D1_MVREF)
N16800565: R52.1 U3.53(~{BYTE})
N16800570: R51.1 U3.16(~{WP}/ACC)
N16821274: R21.1 U1.A17(IFC_CLK0)
N16821816: R14.1 U1.E14(IFC_PERR_B)
N17059126: R124.1 U1.AE7(EC2_TXD0)
N17059132: R126.1 U1.AF7(EC2_TXD1)
N17059135: R128.1 U1.AF6(EC2_TXD2)
N17059138: R130.1 U1.AG5(EC2_TXD3)
N17059149: R134.1 R136.1 U1.AF8(EC2_TX_CTL)
N17059152: C52.1 R137.1 U1.AE8(EC2_GTX_CLK)
N17059732: R129.2 U1.AC3(EC1_TXD3)
N17059733: R125.2 U1.AE4(EC1_TXD1)
N17059734: R127.2 U1.AD3(EC1_TXD2)
N17059735: R133.2 U1.AE3(EC1_TXD0)
N17059985: R131.2 R135.2 U1.AF4(EC1_TX_CTL)
N17060054: C51.2 R132.2 U1.AF3(EC1_GTX_CLK)
N17060498: R138.2 U1.AH3(EMI1_MDC)
N17072443: R115.2 TP2.1(TP) U1.B17(RTC)
N17081955: C56.2 U1.AH11(SD1_RX1_P)
N17081957: C57.2 U1.AG11(SD1_RX1_N)
N17082045: C55.2 U1.AG13(SD1_RX2_N)
N17082047: C58.2 U1.AH13(SD1_RX2_P)
N17082121: C59.2 U1.AH14(SD1_RX3_P)
N17082123: C60.2 U1.AG14(SD1_RX3_N)
N17082287: C1054.1 U1.AB18(SD1_REF_CLK2_P)
N17082300: C1055.1 U1.AA18(SD1_REF_CLK2_N)
N17082319: R146.2 U1.Y20(SD1_IMP_CAL_TX)
N17082346: R145.2 U1.AA12(SD1_IMP_CAL_RX)
N17093364: R144.2 TP9.1(TP) U1.AE5(TSEC_1588_TRIG_IN2)
N17093369: R143.2 TP8.1(TP) U1.AB6(TSEC_1588_TRIG_IN1)
N17093378: R142.2 TP7.1(TP) U1.AC8(TSEC_1588_CLK_IN)
N17113140: R100.1 U1.V2(IIC3_SCL)
N17113141: R102.1 U1.W3(IIC3_SDA)
N17113153: R101.2 U1.V3(IIC2_SCL) U12.14(SCL)
N17113154: R103.2 U1.Y3(IIC2_SDA) U12.15(SDA)
N17113208: R107.2 U12.3(~{RESET})
N17113211: R113.2 U1.C20(FA_ANALOG_G_V)
N17113215: R114.2 U1.B20(FA_ANALOG_PIN)
N17113217: R93.1 U1.F9(SCAN_MODE_B)
N17200088: R59.1 U8.1(~{HOLD}) U8.9(~{WP}) U9.3(~{WP}) U9.7(~{HOLD})
N17200106: R66.2 U8.16(SCK) U9.6(SCK)
N17200115: R61.2 U8.8(SO) U9.2(SO)
N17200136: R65.1 U1.N1(SPI_CLK)
N17200150: R67.1 U1.K1(SDHC_CLK)
N17200329: R57.1 R64.2 U8.15(SI) U9.5(SI)
N17208058: R108.2 U1.P5(DMA1_DREQ0_B)
N17208122: R109.2 U1.V5(DMA2_DREQ0_B)
N17246054: Q4.3(D) R150.1 R151.1 U1.F5(USB1_PWRFAULT)
N17246089: Q5.3(D) R149.1 R155.1 U1.H5(USB2_PWRFAULT)
N17246488: R159.2 U19.3(ISET)
N17246514: L1.4 R162.1 U1.F1(USB1_UDP)
N17246518: L1.1 R163.1 U1.F2(USB1_UDM)
N17246522: L2.4 R164.1 U1.H1(USB2_UDP)
N17246524: L2.1 R165.1 U1.H2(USB2_UDM)
N17246685: R168.2 U1.F4(USB1_UID)
N17246689: R167.2 U1.H4(USB2_UID)
N17246719: C78.1 R166.2 U1.G4(USB_IBIAS_REXT)
N17246771: C78.2 R169.2
N17246861: FB4.1 J5.4
N17246863: FB2.1 J5.8
N17271621: R88.1 U1.L4(IRQ10)
N17271626: R89.1 U1.U3(IRQ11)
N17271631: R91.1 U1.F19(TMP_DETECT_B)
N17321001: R112.1 U13.4(O)
N17321019: D1.2 R112.2
N17423481: J4.5 R119.2
N17423546: J4.6 R116.1
N17736577: R31.1 SW1.16
N17736598: R33.1 SW1.15
N17736619: R35.1 SW1.14
N17736629: R37.1 SW1.13
N17736659: R38.1 SW1.12
N17736669: R39.1 SW1.11
N17736681: R40.1 SW1.10
N17736695: R41.1 SW1.9
N17736739: R42.1 SW2.16
N17736751: R43.1 SW2.15
N17736763: R44.1 SW2.14
N17736781: R45.1 SW2.13
N17736801: R48.1 SW2.11
N17736803: R46.1 SW2.12
N17736817: R47.1 SW2.10
N17736835: R49.1 SW2.9
N17979212: R711.2 R715.2 U1.AD1(EC1_RX_CLK)
N17979230: R714.2 R715.1
N17979244: R710.2 R711.1
N17979345: R716.2 R717.1
N17979374: R712.1 R716.1 U1.AH5(EC2_RX_CLK)
N17979380: R712.2 R713.1
N18178202: R718.1 U80.4(C) U81.4(C)
N20516568: TP1.1(TP) U1.E6(CLK_OUT)
N20517420: TP3.1(TP) U1.AD7(TSEC_1588_CLK_OUT)
N20517422: TP4.1(TP) U1.AF5(TSEC_1588_ALARM_OUT1)
N20517434: TP5.1(TP) U1.AC7(TSEC_1588_ALARM_OUT2)
N20517436: TP6.1(TP) U1.AE6(TSEC_1588_PULSE_OUT1)
N20517448: TP10.1(TP) U1.AD8(TSEC_1588_PULSE_OUT2)
N20562248: TP11.1(TP) U1.Y15(SD1_PLL1_TPA)
N20562257: TP12.1(TP) U1.AB15(SD1_PLL1_TPD)
N20562271: TP13.1(TP) U1.Y19(SD1_PLL2_TPA)
N20562273: TP14.1(TP) U1.AB19(SD1_PLL2_TPD)
N22257590: R23.1 U2.2(1Q1)
N22257592: R24.1 U2.3(1Q2)
N22257594: R25.1 U2.5(1Q3)
N22258098: R27.1 U2.8(1Q5)
N22258100: R28.1 U2.9(1Q6)
N22258102: R29.1 U2.11(1Q7)
N22258104: R30.1 U2.12(1Q8)
N22258216: R26.1 U2.6(1Q4)
N22258634: R32.1 U2.13(2Q1)
N22258636: R34.1 U2.14(2Q2)
N22258638: R36.1 U2.16(2Q3)

Not connected (* = marked no-connect by the designer): J1 8(DQS9_N/NC2)* 19(DQS10_N/NC3)* 30(DQS11_N/NC4)* 41(DQS12_N/NC5)* 52(DQS17_N/NC6)* 78(~{EVENT})* 100(DQS13_N/NC9)* 111(DQS14_N/NC10)* 122(DQS15_N/NC11)* 133(DQS16_N/NC12)* 144(RFU1)* 205(RFU2)* 227(RFU3)* 230(NC19/~{SAVE})* 234(A17/NC20)* 235(C2/NC21)*; J4 2* 8* 10* 14*; U1 A14(IFC_BCTL)* A16(IFC_NDDQS)* A19(IFC_CLK1)* AA5(DMA2_DACK0_B)* AC4(EC1_TX_ER)* AD10(SD1_TX0_P)* AE10(SD1_TX0_N)* C14(IFC_PAR1)* C15(IFC_PAR0)* C16(IFC_CS3_B)* C17(IFC_CS5_B)* C19(IFC_CS7_B)* D18(IFC_CS6_B)* E17(IFC_CS4_B)* F21(TEST_OUT1)* H21(TEST_OUT0)* J20(D1_TPA)* K22(TEST_OUT4)* L6(EMI2_MDC)* M6(EMI2_MDIO)* M22(TEST_OUT5)* N3(SPI_CS3_B)* P22(TEST_OUT7)* R5(DMA1_DDONE0_B)* R6(LP_TMP_DETECT_B)* U5(DMA1_DACK0_B)* U22(TEST_OUT6)* V21(TEST_OUT3)* W21(TEST_OUT2)* Y5(DMA2_DDONE0_B)* Y21(TEST_OUT8)*; U2 17(2Q4)* 19(2Q5)* 20(2Q6)* 22(2Q7)* 23(2Q8)*; U3 27(NC1)* 28(NC2)* 30(NC3)*; U4 A1(NC23)* A2(NC24)* A9(NC26)* A10(NC27)* B1(NC25)* B9(NC28)* B10(NC29)* D6(NC5)* D7(NC6)* D8(NC7)* E3(NC8)* E4(NC9)* E5(NC10)* E6(NC11)* E7(NC12)* E8(NC13)* F3(NC14)* F4(NC15)* F5(NC16)* F6(NC17)* F8(NC18)* G3(DNU1)* G5(LOCK)* G6(NC19)* G7(NC20)* G8(DNU2)* H3(NC21)* H5(NC22)* H6(NC1)* H7(NC2)* J3(NC3)* J5(NC4)* L1(NC30)* L2(NC31)* L9(NC34)* L10(NC35)* M1(NC32)* M2(NC33)* M9(NC36)* M10(NC37)*; U8 3(NC1)* 4(NC2)* 5(NC3)* 6(NC4)* 11(NC5)* 12(NC6)* 13(NC7)* 14(NC8)*

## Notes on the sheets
sheet 1
- T104XRDB
- Page  Description
- Version Control
- 1
- SCHEMATIC PAGE LISTING
- 2
- SYSTEM BLOCK DIAGRAM
- Version
- Date
- Modifications
- 3
- T104X DDR4 MEMORY INTERFACE
- V0.1
- 2014/10
- First release of Schematics
- 4
- T104X IFC INTERFACE
- 5
- T104X NOR and NAND FLASH INTERFACE
- V1.0
- 2014/12
- Released to Manufacturing
- 6
- T104X SPI FLASH and SDHC INTERFACE
- 7
- T104X SYSTEM LOGIC INTERFACE
- 8
- T104X ETHERNET and SERDES INTERFACE
- 9
- SERDES and MDIO MUX/DEMUX SWITCHs
- 10
- T104X USB INTERFACE
- 11
- T104X QE-TDM/DIU MUX/DEMUX
- 12
- T104X POWER SUPPLY
- 13
- T104X PLL FILTERs and GROUND
- 14
- T104X DUART and I2C DEVICE INTERFACE
- 15
- TDM RISER INTERFACE
- 16
- HDMI DISPLAY INTERFACE
- 17
- LVDS PANEL INTERFACE
- 18
- PROFIBUS INTERFACE
- 19
- RGMII ETHERNET PORT 1
- 20
- RGMII ETHERNET PORT 2
- 21
- SGMII ETHERNET PORT
- 22
- SGMII ETHERNET PORT 1
- 23
- SGMII ETHERNET PORT 2
- 24
- QSGMII PHY 1
- 25
- QSGMII PHY 2
- 26
- QSGMII ETHERNET PORTs
- 27
- PCIe X1 SLOT, MINI PCIe and SATA CONNECTORs
- 28
- AURORA PORT
- 29
- CPLD
- 30
- SYSTEM CLOCK GENERATORs
- 31
- SYSTEM CLOCK GENERATORs (cont.)
- 32
- T104X CORE POWER CONVERTOR
- All information is subject to change without notice.
  No warranty, expressed or applied, is made as to the
  accuracy of the information contained herein. This
  schematic is provided for reference purposes only.
  Contact your Freescale representative to obtain the
  latest information on this product.
- 33
- SYSTEM POWER CONVERTORs
- 34
- SYSTEM POWER CONVERTORs (cont.)
- 35
- SYSTEM POWER SWITCHs
- 36
- SYSTEM POWER INPUT
- 37
- MECHANICALs
- 38
- CHANGE LIST
sheet 2
- SYSTEM BLOCK DIAGRAM
- RS232
- RS232 XCVR
- UART1
- DDR4
- I2C1
- DDR4 UDIMM
- ATX Power
- DB9
- 72bit, 2/4GB
- 2x1
- 5V
- 12V
- RS232
- RS232 XCVR
- UART2
- IFC
- NOR FLASH
- 16bit, 128MB
- VCORE
- 1.0V
- USB1
- USB1
- I2C EEPROM
- 1.0V_SVDD
- USB Conn.
- USB2
- USB Protect &
  Power Switch
- USB2
- AT24C256
- 1.2V
- Power
  Regulators
- TypeA x2
- USB CTL
- NAND FLASH
- 8bit, 1GB
- 1.35V_XVDD
- 1.5V
- Thermal Monitor
- 1.8V
- SGMII
- ADT7461
- 2.5V
- RJ45
- MDI
- Magnetics
- MDI
- SGMII PHY
- 2.5V_VPP
- RTL8211DN
- EMI1
- ALTERA CPLD
- 3.3V
- SPI
- SPI FLASH
- EPM570G
- 5V
- RGMII
- 64MB
- 12V
- MDI
- MDI
- RGMII PHY
- Magnetics
- RTL8211E-VL
- RJ45
- SDHC
- Protect
- SDHC
- SD Card
- 2x1
- MDI
- MDI
- RGMII PHY
- RGMII
- SDHC/SDXC
- Magnetics
- RTL8211E-VL
- JTAG
- JTAG
- 1.8V<->3.3V
- COP Conn.
- T1040
- MDI
- MDI
- MDI
- MDI
- QSGMII
- JTAG
- JTAG
- MDI
- MDI
- PHY
- QSGMII
- /T1042
- 1.8V<->3.3V
- MDI
- MAGNETICS
- MDI
- F104S8A
- EMI1
- Aurora Conn.
- RJ45 x8
- AURORA
- T1040
- MDI
- MDI
- PCIe
- MDI
- MDI
- MDI
- MDI
- QSGMII
- PHY
- QSGMII
- I2C2CH4
- PEX x1 SLOT
- MDI
- MDI
- F104S8A
- I2C2CH1
- PCIe
- Mini PCIe Conn.
- SGMII
- RJ45
- MDI
- Magnetics
- MDI
- SGMII PHY
- EMI1
- PCIe
- RTL8211DN
- I2C2CH2
- Mini PCIe Conn.
- T1042
- MDI
- MDI
- SGMII PHY
- SATA
- SATA Conn.
- RJ45
- Magnetics
- RTL8211DN
- SGMII
- QE
- SPI
- TDM Riser Card Conn.
- I2C2CH3
- TMDS
- TMDS
- DVI XCVR
- I2C1
- HDMI
- I2C
- Protect
- CH7301C
- DIU
- QE
- ISOLATE
- PROFIBUS
- HEADER
- DIU MUX
- QE
- DIU
- 74CB3Q3253
- LCD
- LVDS
- DS90C387R
- LDI XCVR
sheet 3
- T104X DDR4 MEMORY INTERFACE
- 1V2_SLP decoupling caps on page 13
- Decoupling between
  1V2 and 1V2_SLP
  power split located under UDIMMS.
  Place these caps around DDR
  Power Pin areas to stitch return
  current flow for Address and
  command signals.
- UNUSED FOR DDR4
- SPD ADDR = 0x51
sheet 4
- T104X IFC INTERFACE
- CS0: NOR or NAND
- CS1: NAND or NOR
- CS2: CPLD
- cfg_test_port_dis
- T104X RESET CONFIGURATION
- cfg_rcw_src[0:8]
- 0_0010_0111: NOR FLASH BOOT
- 0_0100_0000: SD CARD BOOT
- 0_0100_0101: SPI BOOT
- 1_0001_1001: NAND FLASH BOOT
- cfg_rcw_src0
- cfg_rcw_src1
- cfg_rcw_src2
- cfg_rcw_src3
- cfg_rcw_src4
- cfg_rcw_src5
- cfg_rcw_src6
- cfg_rcw_src7
- cfg_rcw_src8
- cfg_ifc_te
- cfg_pll_config_sel_b
- cfg_por_ainit
- cfg_svr0
- cfg_svr1
- cfg_dram_type
- cfg_rsp_dis
sheet 5
- T104X NOR and NAND FLASH INTERFACE
- 128MB 16-BIT NOR FLASH
- 1GB 8-BIT NAND FLASH
sheet 6
- T104X SPI FLASH and SDHC INTERFACE
- 64MB SERIAL FLASH
- EVDD CAN BE 3.3V or 1.8V
- CO-LAYOUT
- SD CARD VDD MANUAL SELECTION
sheet 7
- T104X SYSTEM LOGIC INTERFACE
- TEST_SEL_B
- FOR T1040/T1042, PULL-DOWN
- FOR T1020/T1022, PULL-UP
- cfg_test_port_mux_sel
- XVDD use 1.35V
- I2C ADDR = 0x77
- cfg_xvdd_sel
- LABEL = ASLEEP
- COP CONNECTOR
sheet 8
- T104X ETHERNET and SERDES INTERFACE
- 3 inch delay line
- 3 inch delay line
sheet 9
- SERDES and MDIO MUX/DEMUX SWITCHs
sheet 10
- T104X USB INTERFACE
- USB1&2 FOR HOST MODE
